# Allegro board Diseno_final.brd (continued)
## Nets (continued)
PHIDI_04: J1.11 R140.1
PHIDI_05: J1.2 R119.1
PHIDI_06: J1.3 R122.1
PHIDI_07: J1.4 R125.1
PHIDI_08: J1.5 R128.1
PHIDI_09: J5.8 R155.1
PHIDI_10: J5.9 R158.1
PHIDI_11: J5.10 R161.1
PHIDI_12: J5.11 R164.1
PHIDI_13: J5.2 R143.1
PHIDI_14: J5.3 R146.1
PHIDI_15: J5.4 R149.1
PHIDI_16: J5.5 R152.1
PHIDO_01: J9.8 R181.2
PHIDO_02: J9.9 R184.2
PHIDO_03: J9.10 R187.2
PHIDO_04: J9.11 R190.2
PHIDO_05: J9.2 R169.2
PHIDO_06: J9.3 R172.2
PHIDO_07: J9.4 R175.2
PHIDO_08: J9.5 R178.2
PHIDO_09: J13.8 R193.2
PHIDO_10: J13.9 R196.2
PHIDO_11: J13.10 R199.2
PHIDO_12: J13.11 R202.2
PHIDO_13: J13.2 R205.2
PHIDO_14: J13.3 R208.2
PHIDO_15: J13.4 R211.2
PHIDO_16: J13.5 R214.2
N74747: R120.1 U126.4(Y)
N74829: C157.1 R119.2 R121.1 U126.2(A) U184.3(C/A)
N79416: R123.1 U127.4(Y)
N79462: C158.1 R122.2 R124.1 U127.2(A) U185.3(C/A)
N79945: R126.1 U128.4(Y)
N79991: C159.1 R125.2 R127.1 U128.2(A) U186.3(C/A)
N80527: R129.1 U129.4(Y)
N80573: C160.1 R128.2 R130.1 U129.2(A) U187.3(C/A)
N81079: R131.1 U130.4(Y)
N81125: C161.1 R132.2 R133.1 U130.2(A) U188.3(C/A)
N81639: R134.1 U131.4(Y)
N81689: C162.1 R135.2 R136.1 U131.2(A) U189.3(C/A)
N82212: R137.1 U132.4(Y)
N82258: C163.1 R138.2 R139.1 U132.2(A) U190.3(C/A)
N84241: R141.1 U133.4(Y)
N84291: C164.1 R140.2 R142.1 U133.2(A) U191.3(C/A)
N85989: R168.1 U142.4(Y)
N86434: D65.A D66.C R168.2 R169.1
N87118: R171.1 U143.4(Y)
N87238: D67.A D68.C R171.2 R172.1
N87595: R174.1 U144.4(Y)
N87715: D69.A D70.C R174.2 R175.1
N88084: R177.1 U145.4(Y)
N88204: D71.A D72.C R177.2 R178.1
N88589: R180.1 U146.4(Y)
N88709: D73.A D74.C R180.2 R181.1
N89108: R183.1 U147.4(Y)
N89151: R147.1 U135.4(Y)
N89207: C166.1 R146.2 R148.1 U135.2(A) U193.3(C/A)
N89228: D75.A D76.C R183.2 R184.1
N89405: R150.1 U136.4(Y)
N89461: C167.1 R149.2 R151.1 U136.2(A) U194.3(C/A)
N89641: R186.1 U148.4(Y)
N89659: R153.1 U137.4(Y)
N89709: C168.1 R152.2 R154.1 U137.2(A) U195.3(C/A)
N89761: D77.A D78.C R186.2 R187.1
N89929: R156.1 U138.4(Y)
N89969: C169.1 R155.2 R157.1 U138.2(A) U196.3(C/A)
N90183: R159.1 U139.4(Y)
N90186: R189.1 U149.4(Y)
N90223: C170.1 R158.2 R160.1 U139.2(A) U197.3(C/A)
N90306: D79.A D80.C R189.2 R190.1
N90437: R162.1 U140.4(Y)
N90483: C171.1 R161.2 R163.1 U140.2(A) U198.3(C/A)
N90675: R165.1 U141.4(Y)
N90725: C172.1 R164.2 R166.1 U141.2(A) U199.3(C/A)
N90891: R144.1 U134.4(Y)
N90937: C165.1 R143.2 R145.1 U134.2(A) U192.3(C/A)
N91462: R192.1 U150.4(Y)
N91582: D81.A D82.C R192.2 R193.1
N91694: R195.1 U151.4(Y)
N91818: D83.A D84.C R195.2 R196.1
N91930: R198.1 U152.4(Y)
N92054: D85.A D86.C R198.2 R199.1
N92166: R201.1 U153.4(Y)
N92290: D87.A D88.C R201.2 R202.1
N92402: R204.1 U154.4(Y)
N92526: D89.A D90.C R204.2 R205.1
N92638: R207.1 U155.4(Y)
N92762: D91.A D92.C R207.2 R208.1
N92874: R210.1 U156.4(Y)
N92998: D93.A D94.C R210.2 R211.1
N93110: R213.1 U157.4(Y)
N93154: R79.1 U65.4(VREF) U66.6(OUT)
N93187: C89.2 U65.5(IOUT) U67.2(-IN)
N93234: D95.A D96.C R213.2 R214.1
N93303: C89.1 R82.1 U65.3(RFB) U67.6(OUT)
N93563: D17.A D18.C R82.2 R83.1
N101155: R80.1 R81.2 U64.2(V-)
N101611: R79.2 U66.2(-IN)
N101668: R81.1 U66.3(+IN)
N103431: C87.2 U63.2(VOUT) U67.7(V+)
N104801: R77.1 R78.2 U61.1(V+)
N105129: R78.1 U60.3(+IN_A)
N105257: R76.2 U60.4(-IN_A)
N105843: R5.1 R9.2 U160.3(C/A)
N106132: R5.2 U7.3(+IN)
N106136: R11.2 U7.2(-IN)
N106151: R7.2 R11.1 U7.6(OUT)
N106282: C9.1 R7.1 R8.2
N106462: C10.2 R8.1 U8.3(+IN)
N106606: C9.2 R6.2 R10.1 U8.6(OUT)
N106624: R10.2 R12.1 U8.2(-IN)
N106890: C7.2 U5.2(VOUT) U8.7(V+)
N107081: C5.2 U2.2(VOUT) U7.7(V+)
N108762: C12.2 U7.4(V-) U9.4(-OUT)
N108773: C14.2 U8.4(V-) U10.4(-OUT)
N109129: R6.1 U6.3(VIN)
N109578: R3.2 R223.1 U3.1(OUT)
N109817: C2.2 U1.2(VOUT) U3.5(V+)
N111654: R1.2 R2.1 U4.1(+)
N111746: R2.2 U3.3(+IN)
N111794: R3.1 U3.4(-IN)
N112163: U6.5(SDATA) U168.2(A)
N119962: J10.4 R83.2
N119975: J10.6 R87.2
N119987: J10.7 R93.2
N119999: J10.9 R97.2
N122542: R17.2 R18.1 U161.3(C/A)
N122562: R18.2 U14.3(+IN)
N122563: J14.4 R102.2
N122566: R20.2 U14.2(-IN)
N122567: J14.6 R107.2
N122571: J14.7 R112.2
N122574: R15.2 R20.1 U14.6(OUT)
N122575: J14.9 R117.2
N122594: C19.1 R15.1 R16.2
N122598: C20.2 R16.1 U15.3(+IN)
N122622: C19.2 R14.2 R19.1 U15.6(OUT)
N122634: R19.2 R21.1 U15.2(-IN)
N122662: C17.2 U12.2(VOUT) U15.7(V+)
N122690: C16.2 U11.2(VOUT) U14.7(V+)
N122954: C21.2 U14.4(V-) U16.4(-OUT)
N122958: C24.2 U15.4(V-) U17.4(-OUT)
N122962: R14.1 U13.3(VIN)
N122974: U13.5(SDATA) U169.2(A)
N123518: J3.4 R9.1
N123530: J3.6 R17.1
N123542: J3.7 R23.1
N123554: J3.9 R35.1
N124156: J7.4 R42.1
N124168: J7.6 R52.1
N124183: J7.7 R59.1
N124195: J7.9 R71.1
N124258: R84.1 U73.6(OUT) U74.4(VREF)
N124270: C98.2 U74.5(IOUT) U75.2(-IN)
N124298: C98.1 R86.1 U74.3(RFB) U75.6(OUT)
N124346: D19.A D20.C R86.2 R87.1
N124548: R85.1 R88.2 U72.2(V-)
N124568: R84.2 U73.2(-IN)
N124584: R88.1 U73.3(+IN)
N124764: C97.2 U71.2(VOUT) U75.7(V+)
N124930: R23.2 R27.1 U162.3(C/A)
N124958: R27.2 U21.3(+IN)
N124962: R29.2 U21.2(-IN)
N124970: R25.2 R29.1 U21.6(OUT)
N124990: C29.1 R25.1 R26.2
N124994: C30.2 R26.1 U22.3(+IN)
N125018: C29.2 R24.2 R28.1 U22.6(OUT)
N125030: R28.2 R30.1 U22.2(-IN)
N125058: C27.2 U19.2(VOUT) U22.7(V+)
N125086: C26.2 U18.2(VOUT) U21.7(V+)
N125344: C31.2 U21.4(V-) U23.4(-OUT)
N125348: C34.2 U22.4(V-) U24.4(-OUT)
N125358: R24.1 U20.3(VIN)
N125370: U20.5(SDATA) U170.2(A)
N127346: R35.2 R36.1 U163.3(C/A)
N127374: R36.2 U29.3(+IN)
N127378: R38.2 U29.2(-IN)
N127386: R33.2 R38.1 U29.6(OUT)
N127406: C39.1 R33.1 R34.2
N127410: C40.2 R34.1 U28.3(+IN)
N127434: C39.2 R32.2 R37.1 U28.6(OUT)
N127446: R37.2 R39.1 U28.2(-IN)
N127474: C37.2 U26.2(VOUT) U28.7(V+)
N127502: C36.2 U25.2(VOUT) U29.7(V+)
N127760: C41.2 U29.4(V-) U30.4(-OUT)
N127764: C44.2 U28.4(V-) U31.4(-OUT)
N127774: R32.1 U27.3(VIN)
N127786: U27.5(SDATA) U171.2(A)
N128052: R89.1 U81.4(VREF) U83.6(OUT)
N128064: C107.2 U81.5(IOUT) U82.2(-IN)
N128092: C107.1 R92.1 U81.3(RFB) U82.6(OUT)
N128132: D21.A D22.C R92.2 R93.1
N128330: R90.1 R91.2 U80.2(V-)
N128350: R89.2 U83.2(-IN)
N128366: R91.1 U83.3(+IN)
N128546: C106.2 U79.2(VOUT) U82.7(V+)
N130444: C116.2 U90.5(IOUT) U91.2(-IN)
N130448: R94.1 U89.6(OUT) U90.4(VREF)
N130476: C116.1 R96.1 U90.3(RFB) U91.6(OUT)
N130520: D23.A D24.C R96.2 R97.1
N130722: R95.1 R98.2 U88.2(V-)
N130734: R94.2 U89.2(-IN)
N130754: R98.1 U89.3(+IN)
N130926: C115.2 U87.2(VOUT) U91.7(V+)
N150307: C125.2 U98.5(IOUT) U99.2(-IN)
N150319: R99.1 U97.6(OUT) U98.4(VREF)
N150363: C125.1 R101.1 U98.3(RFB) U99.6(OUT)
N150395: D25.A D26.C R101.2 R102.1
N150597: R100.1 R103.2 U96.2(V-)
N150621: R99.2 U97.2(-IN)
N150641: R103.1 U97.3(+IN)
N150813: C124.2 U95.2(VOUT) U99.7(V+)
N151319: R42.2 R43.1 U164.3(C/A)
N151343: C134.2 U106.5(IOUT) U107.2(-IN)
N151347: R43.2 U36.3(+IN)
N151351: R47.2 U36.2(-IN)
N151355: R104.1 U105.6(OUT) U106.4(VREF)
N151359: R45.2 R47.1 U36.6(OUT)
N151379: C49.1 R41.2 R45.1
N151407: C49.2 R44.2 R46.1 U35.6(OUT)
N151415: D27.A D28.C R106.2 R107.1
N151419: R46.2 R48.1 U35.2(-IN)
N151447: C47.2 U33.2(VOUT) U35.7(V+)
N151475: C46.2 U32.2(VOUT) U36.7(V+)
N151623: R105.1 R108.2 U104.2(V-)
N151641: R104.2 U105.2(-IN)
N151661: R108.1 U105.3(+IN)
N151733: C51.2 U36.4(V-) U37.4(-OUT)
N151737: C54.2 U35.4(V-) U38.4(-OUT)
N151741: R44.1 U34.3(VIN)
N151759: U34.5(SDATA) U172.2(A)
N151833: C133.2 U103.2(VOUT) U107.7(V+)
N152345: R52.2 R54.1 U165.3(C/A)
N152363: C143.2 U114.5(IOUT) U115.2(-IN)
N152375: R109.1 U113.6(OUT) U114.4(VREF)
N152387: R54.2 U43.3(+IN)
N152391: R56.2 U43.2(-IN)
N152399: R50.2 R56.1 U43.6(OUT)
N152403: C143.1 R111.1 U114.3(RFB) U115.6(OUT)
N152419: C59.1 R50.1 R51.2
N152423: C60.2 R51.1 U42.3(+IN)
N152441: D29.A D30.C R111.2 R112.1
N152447: C59.2 R53.2 R55.1 U42.6(OUT)
N152459: R55.2 R57.1 U42.2(-IN)
N152487: C57.2 U40.2(VOUT) U42.7(V+)
N152515: C56.2 U39.2(VOUT) U43.7(V+)
N152649: R110.1 R113.2 U112.2(V-)
N152661: R109.2 U113.2(-IN)
N152681: R113.1 U113.3(+IN)
N152773: C61.2 U43.4(V-) U44.4(-OUT)
N152777: C64.2 U42.4(V-) U45.4(-OUT)
N152781: R53.1 U41.3(VIN)
N152799: U41.5(SDATA) U173.2(A)
N152853: C142.2 U111.2(VOUT) U115.7(V+)
N153383: C152.2 U122.5(IOUT) U123.2(-IN)
N153389: R59.2 R63.1 U166.3(C/A)
N153395: R114.1 U121.6(OUT) U122.4(VREF)
N153423: C152.1 R116.1 U122.3(RFB) U123.6(OUT)
N153431: R63.2 U50.3(+IN)
N153435: R65.2 U50.2(-IN)
N153443: R61.2 R65.1 U50.6(OUT)
N153455: D31.A D32.C R116.2 R117.1
N153463: C69.1 R61.1 R62.2
N153467: C70.2 R62.1 U49.3(+IN)
N153491: C69.2 R60.2 R64.1 U49.6(OUT)
N153503: R64.2 R66.1 U49.2(-IN)
N153531: C67.2 U47.2(VOUT) U49.7(V+)
N153559: C66.2 U46.2(VOUT) U50.7(V+)
N153663: R115.1 R118.2 U120.2(V-)
N153681: R114.2 U121.2(-IN)
N153701: R118.1 U121.3(+IN)
N153817: C71.2 U50.4(V-) U51.4(-OUT)
N153821: C74.2 U49.4(V-) U52.4(-OUT)
N153825: R60.1 U48.3(VIN)
N153843: U48.5(SDATA) U174.2(A)
N153873: C151.2 U119.2(VOUT) U123.7(V+)
N154443: R71.2 R72.1 U167.3(C/A)
N154471: R72.2 U56.3(+IN)
N154475: R74.2 U56.2(-IN)
N154483: R69.2 R74.1 U56.6(OUT)
N154503: C79.1 R69.1 R70.2
N154507: C80.2 R70.1 U57.3(+IN)
N154531: C79.2 R68.2 R73.1 U57.6(OUT)
N154543: R73.2 R75.1 U57.2(-IN)
N154571: C77.2 U54.2(VOUT) U57.7(V+)
N154599: C76.2 U53.2(VOUT) U56.7(V+)
N154857: C81.2 U56.4(V-) U58.4(-OUT)
N154861: C84.2 U57.4(V-) U59.4(-OUT)
N154865: R68.1 U55.3(VIN)
N154883: U55.5(SDATA) U175.2(A)
N183704: U65.2(SDI) U176.4(Y)
N189418: R4.1 U168.4(Y)
N189529: R40.1 U172.4(Y)
N189636: R13.1 U169.4(Y)
N189665: R49.1 U173.4(Y)
N189787: R22.1 U170.4(Y)
N189811: R58.1 U174.4(Y)
N189953: R31.1 U171.4(Y)
N189979: R67.1 U175.4(Y)
N190257: U74.2(SDI) U177.4(Y)
N190390: U98.2(SDI) U180.4(Y)
N190419: U81.2(SDI) U178.4(Y)
N190547: U106.2(SDI) U181.4(Y)
N190594: U90.2(SDI) U179.4(Y)
N190692: U114.2(SDI) U182.4(Y)
N190839: U122.2(SDI) U183.4(Y)
N222678: C91.2 U66.4(V-) U68.4(-OUT)
N222700: C127.2 U97.4(V-) U100.4(-OUT)
N224115: C129.2 U99.4(V-) U101.4(-OUT)
N224126: C93.2 U67.4(V-) U69.4(-OUT)
N225476: C100.2 U73.4(V-) U76.4(-OUT)
N225794: C136.2 U105.4(V-) U108.4(-OUT)
N226643: C102.2 U75.4(V-) U77.4(-OUT)
N226662: C138.2 U107.4(V-) U109.4(-OUT)
N227931: C109.2 U83.4(V-) U84.4(-OUT)
N229062: C111.2 U82.4(V-) U85.4(-OUT)
N230061: C118.2 U89.4(V-) U92.4(-OUT)
N231120: C120.2 U91.4(V-) U93.4(-OUT)
N231215: C154.2 U121.4(V-) U124.4(-OUT)
N232018: C156.2 U123.4(V-)
N233016: C145.2 U113.4(V-) U116.4(-OUT)
N233815: C147.2 U115.4(V-) U117.4(-OUT)
N255947: U300.3(VCCCIO0#3)

Pads without a net: U7 1 5 8; U8 1 5 8; U9 1 3; U10 1 3; U14 1 5 8; U15 1 5 8; U16 1 3; U17 1 3; U21 1 5 8; U22 1 5 8; U23 1 3; U24 1 3; U28 1 5 8; U29 1 5 8; U30 1 3; U31 1 3; U35 1 5 8; U36 1 5 8; U37 1 3; U38 1 3; U42 1 5 8; U43 1 5 8; U44 1 3; U45 1 3; U49 1 5 8; U50 1 5 8; U51 1 3; U52 1 3; U56 1 5 8; U57 1 5 8; U58 1 3; U59 1 3; U62 4; U66 1 5 8; U67 1 5 8; U68 1 3; U69 1 3; U73 1 5 8; U75 1 5 8; U76 1 3; U77 1 3; U82 1 5 8; U83 1 5 8; U84 1 3; U85 1 3; U89 1 5 8; U91 1 5 8; U92 1 3; U93 1 3; U97 1 5 8; U99 1 5 8; U100 1 3; U101 1 3; U105 1 5 8; U107 1 5 8; U108 1 3; U109 1 3; U113 1 5 8; U115 1 5 8; U116 1 3; U117 1 3; U121 1 5 8; U123 1 5 8; U124 1 3; U126 1; U127 1; U128 1; U129 1; U130 1; U131 1; U132 1; U133 1; U134 1; U135 1; U136 1; U137 1; U138 1; U139 1; U140 1; U141 1; U142 1; U143 1; U144 1; U145 1; U146 1; U147 1; U148 1; U149 1; U150 1; U151 1; U152 1; U153 1; U154 1; U155 1; U156 1; U157 1; U168 1; U169 1; U170 1; U171 1; U172 1; U173 1; U174 1; U175 1; U176 1; U177 1; U178 1; U179 1; U180 1; U181 1; U182 1; U183 1; U200 1; U201 1; U202 1; U203 1; U204 1; U205 1; U206 1; U207 1; U208 1; U209 1; U210 1; U211 1; U212 1; U213 1; U214 1; U215 1; U300 15 16 17 18 19 20 21 22 25 26 27 28 29 30 51 52 55 56 57 58 69 70 71 72 75 76 77 78 86 88 90 93 94 95 96 97 98 99 100 101 102 117 118 119 120 121 122 125 126 127 128 129 130 145 146 147 148 149 150 151 152 155 156 157 158 161 162 163 164; U301 1 4 5 6 7 8 10 12 13 15 17 18 19 20 21 24; U302 1 4 5 6 7 8 9 10 11 12 13 15 17 18 19 20 21 24

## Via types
v1: diameter 0.61, hole 0.33, TOP to BOTTOM, 885 vias

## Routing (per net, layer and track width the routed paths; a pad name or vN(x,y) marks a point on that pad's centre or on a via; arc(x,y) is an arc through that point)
3V3: length 493.2
  TOP w0.381: C237.1 119.56,48.45 118.58,47.47 v1(117.96,47.47) 117.27,48.16 U154.5 ; U202.5 v1(121.64,105.82) ; v1(100.33,40.69) 100.33,41.69 100.34,41.69 U144.5 ; U171.5 106.69,171.46 106.69,171.45 106.45,171.45 106.2,171.2 106.2,170.59 ; U138.5 55.27,53.29 v1(54.38,54.18) 53.24,54.18 52.93,53.87 C221.1 ; 106.2,170.59 v1(105.13,170.59) ; 106.2,170.59 106.2,169.91 107,169.11 C190.1 ; C192.1 v1(121.31,172.72) ; C206.1 v1(112.09,127.89) ; v1(122.05,87.53) 121.23,88.34 C241.1 ; C194.1 v1(105.36,107.21) 105.36,107.84 105.38,107.86 105.38,108.38 106.6,109.6 U173.5 ; C201.1 v1(111.96,148.62) ; U215.5 v1(121.94,162.27) ; v1(115.06,41.3) 115.41,41.65 U150.5 ; U132.5 38.84,53.24 v1(38.2,53.87) 37.36,53.87 36.68,53.19 C215.1 ; C203.1 v1(111.86,176) ; v1(133.05,41.21) 133.05,41.22 133.05,42.63 U153.5 ; C244.1 v1(121.95,123.39) ; C219.1 64.9,46.33 65.41,46.84 65.68,46.84 65.71,46.86 v1(66.4,46.86) 67.11,46.15 U136.5 ; C222.1 59.97,53.43 60.29,53.75 v1(61.54,53.75) 62.18,53.11 U139.5 ; C240.1 137.29,48.65 136.49,47.85 v1(135.41,47.85) 134.92,48.34 U157.5 ; C204.1 v1(121.95,158.65) ; U137.5 73.94,46.18 v1(73.25,46.86) 72.21,46.86 71.73,46.38 C220.1 ; U206.5 v1(106.49,165.9) ; C213.1 22.94,53.62 v1(23.93,54.61) 25.17,53.37 U130.5 ; C185.1 120.8,102.13 v1(121.67,101.27) ; U181.5 v1(112.11,131.55) ; U211.5 v1(121.36,120.02) ; U126.5 22.96,46.03 v1(22.33,46.66) 21.16,46.66 20.39,45.88 C209.1 ; C191.1 v1(106.5,162.33) ; U205.5 v1(112.45,145.29) ; U141.5 75.92,53.45 75.58,53.8 v1(74.96,53.8) 74.12,53.8 73.74,53.42 C224.1 ; C207.1 v1(112.04,155.37) ; U155.5 123.16,48.47 123.65,47.98 v1(123.65,47.96) 124.83,47.96 125.45,48.58 C238.1 ; v1(121.34,116.92) 120.93,116.51 C197.1 ; U131.5 32,53.3 31.64,53.67 v1(31.01,53.67) 30.34,53.67 29.77,53.1 C214.1 ; C202.1 v1(121.28,179.73) ; v1(121.46,94.36) 120.88,94.95 C243.1 ; v1(88.24,40.79) 88.29,40.79 88.57,41.07 U142.5 ; C242.1 v1(112.12,93.65) ; U174.5 115.86,139.83 114.83,138.8 v1(114.83,137.54) C195.1 ; C210.1 27.36,45.88 28.08,46.61 v1(29.41,46.61) 29.79,46.23 U127.5 ; C218.1 57.96,46.15 58.72,46.91 v1(59.61,46.91) 59.76,46.9 60.2,46.46 U135.5 ; U143.5 94.45,41.69 94.44,41.68 v1(94.44,40.72) ; v1(106.22,40.79) 106.22,41.5 U145.5 ; U203.5 v1(112.21,117.82) ; U156.5 129.04,48.79 v1(129.62,48.21) 130.97,48.21 131.37,48.6 C239.1 ; C186.1 v1(112.12,114.15) ; C198.1 v1(111.96,121.06) ; C181.1 v1(105.41,79.76) 105.41,80.88 106.69,82.16 U168.5 ; U183.5 v1(112.16,186.51) ; C223.1 66.93,53.23 67.37,53.67 v1(68.45,53.67) 69.09,53.04 U140.5 ; U178.5 v1(121.7,155.22) ; U148.5 102.22,48.28 v1(102.79,47.7) 103.67,47.7 104.6,48.63 C230.1 ; U207.5 v1(121.33,176.35) ; U204.5 v1(121.55,134.1) ; C231.1 110.44,48.34 109.75,47.65 v1(108.8,47.65) 108.1,48.35 U149.5 ; C217.1 51.05,46.23 51.74,46.91 v1(52.51,46.91) 53.29,46.14 U134.5 ; U179.5 v1(121.28,183.39) ; C189.1 v1(112.42,141.73) ; C205.1 v1(112.14,100.33) ; C187.1 v1(105.56,134.82) 105.56,136.02 106.66,137.11 U170.5 ; C193.1 116.13,81.15 v1(113.79,83.49) 116.8,83.49 U172.5 ; U176.5 v1(121.51,98.68) ; U201.5 v1(112.48,90.34) ; U152.5 127.18,41.43 126.72,40.97 v1(126.62,40.97) ; C211.1 34.11,46.05 34.82,46.76 v1(36,46.76) 36.63,46.14 U128.5 ; U209.5 v1(121.99,91.86) ; U200.5 v1(121.34,77.77) ; C184.1 116.05,110.01 v1(113.82,112.24) U169.5 ; 90.45,49.57 U146.5 90.45,48.62 91.21,47.85 v1(91.21,47.65) 91.26,47.6 92.02,47.6 92.74,48.31 C232.1 ; C182.1 v1(121.31,73.89) ; U214.5 v1(111.87,179.64) ; C216.1 43.46,53.44 43.81,53.8 v1(45.19,53.8) 45.67,53.31 U133.5 ; C183.1 v1(112.29,86.72) ; U147.5 96.33,47.99 v1(96.65,47.68) 97.68,47.68 98.63,48.63 C229.1 ; C200.1 v1(121.87,144.6) ; C196.1 v1(114.83,165.71) 114.83,167 115.83,168 U175.5 ; C212.1 41.12,45.9 41.99,46.76 v1(43.08,46.76) 43.46,46.38 U129.5 ; U182.5 v1(112.06,159.03) ; C199.1 v1(121.79,151.56) ; U212.5 v1(112.05,152.16) ; C188.1 v1(121.51,130.43) ; U210.5 v1(112.06,124.68) ; v1(120.83,40.94) 121.29,41.41 U151.5 ; U213.5 v1(121.79,148.18) ; C208.1 v1(111.81,182.83) ; U208.5 v1(112.2,97.21) ; U180.5 v1(112,104.08) ; U177.5 v1(122.11,127.06)
  VCC w0.127: J9.7 91.34,17.51 ; J9.7 92.22,16.64 ; J9.7 90.46,16.64 ; J9.7 91.34,15.76 ; U302.14 61.42,162.25 ; U302.14 60.41,161.24 ; U302.14 60.41,163.27 ; U302.14 59.39,162.25 ; J5.7 56.63,16.64 ; J5.7 54.88,16.64 ; J5.7 55.75,15.76 ; J5.7 55.75,17.51 ; J5.6 69.33,14.1 ; J5.6 68.45,14.97 ; J5.6 67.58,14.1 ; J5.6 68.45,13.22 ; 103.16,14.1 J9.6 ; J9.6 104.92,14.1 ; J9.6 104.04,13.22 ; J9.6 104.04,14.97 ; 113.32,16.64 J13.7 ; J13.7 114.2,17.51 ; J13.7 114.2,15.76 ; J13.7 115.08,16.64 ; J1.6 45.59,14.97 ; J1.6 45.59,13.22 ; J1.6 46.47,14.1 ; J1.6 44.72,14.1 ; J13.6 127.78,14.1 ; J13.6 126.02,14.1 ; J13.6 126.9,14.97 ; J13.6 126.9,13.22 ; 32.89,15.76 J1.7 ; J1.7 32.02,16.64 ; J1.7 33.77,16.64 ; J1.7 32.89,17.51
  BOTTOM w0.381: v1(31.01,53.67) 31.87,52.81 U185.2 ; R209.2 v1(128.75,62.48) ; v1(126.62,40.97) 126.18,40.97 ; 126.18,40.97 124.54,40.97 123.67,41.83 C235.1 ; 126.18,40.97 125.94,40.73 D85.C ; C227.1 96.75,41.95 97.57,41.13 99.89,41.13 v1(100.33,40.69) 99.58,40.69 99.12,40.22 D69.C ; D89.C 117.19,40.52 v1(116.36,41.35) ; C233.1 111.81,41.95 112.46,41.3 v1(115.06,41.3) 114.62,40.86 114.62,40.82 114.27,40.47 D81.C ; v1(107.77,65.68) 104.83,62.74 R176.2 ; 132.27,41.15 132.33,41.21 v1(133.05,41.21) ; 132.27,41.15 131.77,40.65 D87.C ; 132.27,41.15 130.18,41.15 129.54,41.78 C236.1 ; R188.2 107.72,63.35 v1(108.89,64.52) ; C226.1 90.91,42.21 91.36,41.76 93.4,41.76 v1(94.44,40.72) 93.81,40.72 93.28,40.19 D67.C ; U196.2 59,55.7 59.33,56.03 v1(61.11,56.03) ; v1(102.72,40.64) 102.71,40.64 102.03,39.96 D77.C ; v1(74.68,56.01) 73.15,56.01 72.8,55.66 U198.2 ; v1(61.54,53.75) 62.04,53.25 U193.2 ; U189.2 35.22,55.64 35.59,56.01 36.15,56.01 36.59,55.56 v1(36.59,54.94) ; v1(96.93,40.69) 96.2,39.96 D75.C ; v1(67.84,56.09) 66.17,56.09 65.9,55.82 U197.2 ; R206.2 v1(122.96,63.3) ; R173.2 v1(99.03,62.79) ; R203.2 v1(117.17,63.32) ; v1(50.57,55.65) 50.01,56.21 49.59,56.21 49.02,55.64 U191.2 ; C234.1 117.73,41.97 118.78,40.92 119.02,40.92 119.05,40.94 120.36,40.94 ; R200.2 v1(131.65,62.41) ; R185.2 v1(101.93,62.79) ; U188.2 28.32,55.64 28.63,55.95 29.17,55.95 v1(29.79,55.32) ; D83.C 120.11,40.69 120.36,40.94 ; 120.36,40.94 v1(120.83,40.94) ; R197.2 v1(125.86,62.48) ; v1(108.74,41) 107.86,40.12 D79.C ; R167.2 v1(87.45,62.69) ; R179.2 v1(90.35,62.66) ; U195.2 75.84,52.91 v1(74.96,53.8) ; U186.2 38.77,53.31 v1(38.2,53.87) ; v1(23.93,54.61) 23.93,53.99 24.97,52.95 U184.2 ; v1(127.91,41.11) 128.53,41.11 128.85,40.79 D93.C ; D91.C 123.02,40.85 122.67,41.2 v1(122.05,41.2) ; v1(54.38,54.18) 55.14,53.42 U192.2 ; v1(81.46,55.02) 80.54,55.93 80,55.93 79.7,55.64 U199.2 ; U194.2 68.94,53.18 v1(68.45,53.67) ; v1(45.19,53.8) 45.67,53.31 U187.2 ; U190.2 42.12,55.64 42.4,55.92 42.99,55.92 v1(43.64,55.27) ; R194.2 v1(120.07,63.37) ; D95.C 134.69,40.63 v1(135.56,41.5) ; D71.C 104.95,40.14 105.6,40.79 v1(106.22,40.79) 105.64,41.38 103.09,41.38 102.57,41.9 C228.1 ; R191.2 v1(114.27,63.27) ; D65.C 87.45,39.96 87.8,40.31 87.8,40.35 v1(88.24,40.79) 86.12,40.79 84.86,42.05 C225.1 ; D73.C 90.37,39.96 v1(91.25,40.84) ; R170.2 v1(93.24,62.64) ; R212.2 v1(134.54,62.43) ; R182.2 v1(96.14,62.71)
3V3ADC: length 88.7
  TOP w0.381: 155.6,153.29 156.55,153.29 156.71,153.14 v1(158.06,153.14) ; v1(157.66,112.5) 156.81,112.5 156.55,112.75 U13.1 ; v1(193.32,71.79) 192.38,71.79 192.04,72.14 U34.1 ; U6.1 156.55,72.14 156.83,71.86 v1(157.58,71.86) ; U55.1 192.44,194.72 192.8,194.36 v1(193.42,194.36) ; v1(193.34,112.47) 192.32,112.47 192.04,112.75 U41.1 ; 191.08,153.29 192.04,153.29 192.32,153.01 v1(193.17,153.01) ; v1(157.81,194.45) 156.82,194.45 156.55,194.72 U27.1
  BOTTOM w0.381: v1(193.14,170.66) 191.97,169.49 ; C174.2 156.1,110.62 157.66,112.18 v1(157.66,112.5) ; C173.2 156.04,70.03 157.58,71.56 v1(157.58,71.86) ; C177.2 191.63,70.1 v1(193.32,71.79) ; v1(193.34,112.47) 192.9,112.03 192.89,112.03 191.76,110.9 C178.2 ; C175.2 156.1,151.16 157.62,152.68 157.62,152.7 v1(158.06,153.14) ; C179.2 191.31,151.16 v1(193.17,153.01) ; v1(193.42,194.36) 192.98,193.92 192.97,193.92 191.6,192.56 C180.2 ; 158.47,162.43 v1(156.77,162.43) ; v1(157.81,194.45) 155.79,192.43 C176.2 ; 181.03,160.66 180.23,159.86 R223.2 176.95,159.86
  BOTTOM w1.143: 191.97,169.49 190.8,168.33 188.7,168.33 181.03,160.66 ; 176.95,159.86 168.41,159.86 165.84,162.43 158.47,162.43
3V3DAC: length 56.1
  TOP w0.381: U81.7 233.38,141.48 234.31,140.54 v1(235.2,140.54) ; U106.7 265.91,107.21 266.85,106.27 v1(267.74,106.27) ; U90.7 233.38,175.51 234.31,174.57 v1(235.2,174.57) ; v1(267.74,74.6) 266.85,74.6 265.91,75.54 U98.7 ; U122.7 265.91,175.51 266.85,174.57 v1(267.74,174.57) ; U114.7 265.91,141.48 266.85,140.54 v1(267.74,140.54) ; v1(235.2,106.27) 234.31,106.27 233.38,107.21 U74.7 ; v1(235.2,74.6) 234.31,74.6 233.38,75.54 U65.7
  BOTTOM w0.381: v1(269.06,125.27) 269.02,125.23 269.02,124.38 269.47,123.92 ; 274.05,121.37 274.64,120.78 C86.2 ; 274.05,124.68 274.95,125.58 U62.5 ; v1(255.55,123.92) 256.97,123.92
  BOTTOM w1.27: 274.05,123.92 256.97,123.92 ; 274.05,123.92 274.05,124.68 ; 274.05,123.92 274.05,121.37
3VPROT: length 206.2
  BOTTOM w0.381: 151.76,34.63 152.16,34.24 ; 151.76,34.63 151.76,34.54 151.38,34.16 148.92,34.16 148.46,34.62 U60.1 ; 151.76,34.63 R76.1 ; U166.2 199.22,28.3 198.83,28.69 198.83,29.18 ; 169.65,28.68 169.65,28.33 169.94,28.04 U162.2 ; U165.2 192.65,28.3 192.23,28.71 192.23,29.11 ; 154.91,28.96 154.91,28.44 155.31,28.04 U160.2 ; 185.95,29.11 185.95,28.79 186.47,28.27 U164.2 ; D31.C 268.17,24.41 267.65,23.88 ; U167.2 205.63,28.32 205.13,28.82 205.13,29.24 ; D27.C 257.68,23.88 ; 224.46,24.69 D17.C ; 234.39,24.56 D21.C ; 176.5,28.78 176.5,28.36 176.82,28.04 U163.2 ; 229.39,24.49 D19.C ; 162.99,28.54 163.49,28.04 U161.2 ; 252.76,23.88 D25.C ; 239.88,24.79 D23.C ; D29.C 262.66,23.88
  BOTTOM w0.762: 152.16,34.24 196.98,34.24 197,34.26 207.11,34.26 207.14,34.24 210.13,34.24 220.47,23.9 224.46,23.9 ; 234.39,23.88 239.88,23.88 ; 234.39,23.88 229.41,23.88 229.39,23.9 ; 234.39,23.88 234.39,23.88 234.39,24.56 ; 239.88,23.88 267.65,23.88 ; 239.88,23.88 239.88,24.79 ; 229.39,23.9 229.39,24.49 ; 229.39,23.9 224.46,23.9 ; 224.46,23.9 224.46,24.69
  BOTTOM w0.889: 205.13,34.26 205.13,29.24 ; 198.83,29.18 198.83,34.24 198.81,34.26 ; 192.23,34.24 192.23,29.11 ; 169.65,34.24 169.65,28.68 ; 185.85,34.24 185.95,34.14 185.95,29.11 ; 176.5,28.78 176.5,34.19 176.45,34.24 ; 162.99,28.54 162.79,28.74 162.79,34.24 ; 154.91,28.96 154.91,34.24
5VU: length 188.6
  TOP w0.254: 37.31,131.48 37.81,130.98 U300.83 ; 37.31,131.48 37.05,131.48 36.81,131.24 U300.81 ; 37.31,131.48 38.05,131.48 38.31,131.22 U300.84 ; 37.31,131.48 U300.82
  TOP w0.381: v1(132.84,186.39) 132.84,187.01 132.79,187.06 132.79,190.88 ; v1(18.87,147.96) 18.87,149.3 ; 37.31,131.48 v1(37.31,132.84) ; 23.22,192.81 v1(23.22,190.27)
  TOP w1.27: 18.87,149.3 18.87,150.7 ; 18.87,150.7 17.38,150.7 16.11,151.97 U303.1_1 ; 18.87,150.7 20.95,150.7 22.11,151.85 U303.1_2
  TOP w2.54: 132.79,190.88 127.3,196.37 26.77,196.37 23.22,192.81
  VCC w0.127: J10.2 228.26,16.64 ; J10.2 227.38,15.76 ; J10.2 226.5,16.64 ; J10.2 227.38,17.51 ; 36.53,162.25 U302.23 ; U302.23 37.55,163.27 ; U302.23 38.56,162.25 ; U302.23 37.55,161.24 ; J14.11 262.94,14.97 ; J14.11 262.94,13.22 ; J14.11 263.82,14.1 ; J14.11 262.06,14.1 ; J14.2 250.24,17.51 ; J14.2 250.24,15.76 ; J14.2 251.12,16.64 ; J14.2 249.36,16.64 ; J3.2 168.77,16.64 ; J3.2 167.89,17.51 ; J3.2 167.89,15.76 ; J3.2 167.02,16.64 ; 39.07,187.63 U301.22 ; U301.22 40.09,188.65 ; U301.22 40.09,186.61 ; U301.22 41.1,187.63 ; 36.53,187.63 U301.23 ; U301.23 37.55,186.61 ; U301.23 38.56,187.63 ; U301.23 37.55,188.65 ; J7.11 204.33,14.1 ; J7.11 203.45,13.22 ; J7.11 203.45,14.97 ; J7.11 202.58,14.1 ; J10.11 240.08,14.97 ; J10.11 240.96,14.1 ; J10.11 239.2,14.1 ; J10.11 240.08,13.22 ; 39.07,162.25 U302.22 ; U302.22 40.09,163.27 ; U302.22 41.1,162.25 ; U302.22 40.09,161.24 ; 190.75,15.76 J7.2 ; J7.2 190.75,17.51 ; J7.2 189.88,16.64 ; J7.2 191.63,16.64 ; 180.59,13.22 J3.11 ; J3.11 181.47,14.1 ; J3.11 180.59,14.97 ; J3.11 179.72,14.1
+5V: length 320.7
  VCC w0.127: 59.39,187.63 U301.14 ; U301.14 60.41,186.61 ; U301.14 60.41,188.65 ; U301.14 61.42,187.63
  BOTTOM w0.381: v1(280.62,70.82) 279.5,70.82 ; 146.35,62.41 146.74,62.79 U5.3 ; 174.83,174.42 v1(175.9,174.42) ; 181.86,181.45 182.4,180.92 C78.2 ; C150.2 274.22,172.92 274.76,172.38 ; 146.15,175.92 146.69,176.46 U25.3 ; U12.3 146.61,103.4 146.07,102.86 ; 146.25,134.65 146.63,135.03 147.05,135.03 147.05,135.03 U18.3 ; 146.07,99.49 146.61,98.95 C18.2 ; 146.35,58.87 146.89,58.34 C8.2 ; v1(279.4,136.86) 277.93,136.86 ; 146.13,131.37 146.91,130.58 C25.2 ; 145.06,132.69 v1(144.04,132.69) ; C132.2 274.34,104.62 274.88,104.08 ; C15.2 146.91,90.04 146.3,90.65 ; 245.97,102.87 246.02,102.92 v1(248.44,102.92) ; 178.46,183.13 v1(177.34,183.13) ; 178.23,144.02 178.21,144.02 v1(177.5,144.73) ; C35.2 146.91,172.01 146.15,172.77 ; 181.71,143.18 182.47,143.94 U47.3 ; 272.03,134.7 U111.3 274.14,134.7 ; 240.28,72.95 C88.2 241.35,72.95 241.58,72.72 ; v1(176.99,101.17) 178.26,101.17 ; 272.64,72.95 C123.2 273.94,72.95 274.62,72.26 ; 178.46,60.4 v1(177.11,60.4) ; 274.88,101.04 274.27,100.43 U103.3 272.06,100.43 ; v1(285,122.39) C85.2 281.14,122.39 279.83,123.7 U62.3 ; 146.43,50.11 147.12,49.43 C4.2 ; U2.3 147.05,53.88 146.43,53.26 ; 172.64,166.47 R1.1 172.64,167.79 v1(171.98,168.45) ; v1(176.63,92.15) 178.05,92.15 ; 181.86,184.76 182.45,185.34 183.64,185.34 ; 182.16,139.47 183.56,139.47 C68.2 ; 145.11,60.48 v1(144.15,60.48) ; 241.58,135.25 241.02,134.7 U79.3 239.42,134.7 ; U39.3 182.23,94.5 181.58,93.85 ; 182.32,172.01 C75.2 183.62,172.01 ; U119.3 274.04,168.73 ; 172.1,171.85 172.68,171.27 U1.3 173.71,171.27 ; v1(177.24,180.54) 178.28,180.54 ; 272.77,138.89 C141.2 274.35,138.89 274.88,138.35 ; 245.26,167.23 245.29,167.23 v1(246.46,166.07) ; 241.91,69.3 241.37,68.76 U63.3 239.45,68.76 ; 146.3,93.75 147.05,94.5 U11.3 ; U60.5 v1(148.46,40.36) ; U40.3 182.35,103.4 181.79,102.84 ; 145.82,140.03 146.36,139.49 C28.2 ; v1(280.47,102.77) 278.82,102.77 ; 239.47,100.43 U71.3 241.12,100.43 241.22,100.53 ; 181.86,62.11 182.54,62.79 U33.3 ; 241.97,138.35 241.43,138.89 C105.2 240.28,138.89 ; 241.63,169.11 241.25,168.73 U87.3 239.52,168.73 ; 241.76,104.62 C96.2 240.18,104.62 ; 182.2,58.34 183.57,58.34 C48.2 ; 144.68,141.71 v1(143.56,141.71) ; C45.2 182.35,49.43 181.81,49.97 ; 271.91,68.76 U95.3 274.02,68.76 ; 146.35,181.45 146.89,180.92 C38.2 ; U32.3 182.25,53.88 181.91,53.54 ; C55.2 182.22,90.04 ; 182.02,176.45 183.51,176.45 U53.3 ; U19.3 146.2,143.94 ; v1(280.42,126.8) 280.42,126.17 279.82,125.58 U62.1 ; v1(248.44,71.09) 246.84,71.09 ; C58.2 182.13,98.95 ; 241.63,172.41 241.11,172.92 C114.2 240.23,172.92 ; v1(176.99,132.56) 178.16,132.56 ; 144.53,183.16 v1(143.28,183.16) ; 145.03,51.51 v1(143.89,51.51) ; v1(247.47,137.11) 246.23,137.11 ; 178.82,51.56 v1(177.34,51.56) ; C1.2 172.49,177.11 ; U26.3 146.74,185.37 ; 145.21,92.13 v1(144.07,92.13) ; 144.75,174.27 v1(143.69,174.27) ; U46.3 182.54,135.03 182,134.5 ; 145.03,101.02 v1(143.69,101.02) ; R77.2 v1(152.42,31.15) ; C65.2 182.38,130.58 ; v1(278.76,170.99) 277.5,170.99
  BOTTOM w0.762: 182.2,58.34 181.86,58.68 181.86,60.4 ; 181.86,183.13 178.46,183.13 ; 181.86,183.13 181.86,184.76 ; 181.86,183.13 181.86,181.45 ; 242.12,102.87 242.12,104.26 241.76,104.62 ; 242.12,102.87 245.97,102.87 ; 242.12,102.87 242.12,101.43 241.22,100.53 ; 241.91,69.3 241.91,71.08 241.89,71.09 ; 245.26,167.23 241.76,170.74 241.63,170.74 ; 146.35,183.16 146.35,184.99 146.74,185.37 ; 146.35,183.16 146.35,181.45 ; 146.35,183.16 144.53,183.16 ; 279.5,70.82 274.62,70.82 ; 274.62,70.82 274.62,72.26 ; 274.62,70.82 274.62,69.37 274.02,68.76 ; 146.15,174.27 146.15,175.92 ; 146.15,174.27 144.75,174.27 ; 146.15,174.27 146.15,172.77 ; 181.71,143.18 181.71,141.48 ; 181.71,141.48 181.71,139.92 182.16,139.47 ; 181.71,141.48 180.77,141.48 178.23,144.02 ; 274.88,101.04 274.88,102.77 ; 274.88,102.77 274.88,104.08 ; 274.88,102.77 278.82,102.77 ; 146.35,62.41 146.35,60.48 ; 146.35,60.48 146.35,58.87 ; 146.35,60.48 145.11,60.48 ; 274.14,134.7 274.88,135.44 274.88,136.86 ; 181.86,60.4 178.46,60.4 ; 181.86,60.4 181.86,62.11 ; 274.88,138.35 274.88,136.86 ; 274.88,136.86 277.93,136.86 ; 241.63,172.41 241.63,170.74 ; 241.63,170.74 241.63,169.11 ; 277.5,170.99 274.76,170.99 ; 274.76,170.99 274.76,169.45 274.04,168.73 ; 274.76,170.99 274.76,172.38 ; 146.3,92.13 146.3,93.75 ; 146.3,92.13 145.21,92.13 ; 146.3,92.13 146.3,90.65 ; 182.32,172.01 182.02,172.31 182.02,177.95 179.43,180.54 178.28,180.54 ; 181.81,51.56 181.81,53.44 181.91,53.54 ; 181.81,51.56 181.81,49.97 ; 181.81,51.56 178.82,51.56 ; 146.13,131.37 146.13,132.69 ; 146.13,132.69 145.06,132.69 ; 146.13,132.69 146.13,134.52 146.25,134.65 ; 146.43,51.51 145.03,51.51 ; 146.43,51.51 146.43,53.26 ; 146.43,51.51 146.43,50.11 ; 172.1,171.85 172.1,174.42 ; 172.1,174.42 172.1,176.73 172.49,177.11 ; 172.1,174.42 174.83,174.42 ; 178.26,101.17 181.79,101.17 ; 181.79,101.17 181.79,99.29 182.13,98.95 ; 181.79,101.17 181.79,102.84 ; 246.23,137.11 241.97,137.11 ; 241.97,137.11 241.97,138.35 ; 241.97,137.11 241.97,135.64 241.58,135.25 ; 182.38,130.58 182,130.96 182,132.56 ; 145.82,141.71 145.82,143.56 146.2,143.94 ; 145.82,141.71 144.68,141.71 ; 145.82,141.71 145.82,140.03 ; 241.89,71.09 246.84,71.09 ; 241.89,71.09 241.89,72.41 241.58,72.72 ; 181.58,93.85 181.58,92.15 ; 181.58,92.15 181.58,90.68 182.22,90.04 ; 181.58,92.15 178.05,92.15 ; 178.16,132.56 182,132.56 ; 182,132.56 182,134.5 ; 146.07,101.02 145.03,101.02 ; 146.07,101.02 146.07,102.86 ; 146.07,101.02 146.07,99.49
-5V: length 263.5
  VCC w0.127: U301.11 60.41,173.41 ; U301.11 59.39,172.39 ; U301.11 60.41,171.37 ; U301.11 61.42,172.39
  VCC w0.381: 153.34,190.73 v1(153.34,189.18)
  VCC w1.27: 153.34,192.02 153.34,190.73
  BOTTOM w0.381: U10.5 163.14,59.64 162.71,60.07 162.71,62.2 163.09,62.59 C13.2 164.12,64.61 v1(164.52,65) ; 256.03,174.47 256.01,174.45 C153.2 v1(256.01,171.45) ; U100.5 255.63,75.77 256.01,75.39 C126.2 v1(256.01,71.32) ; C82.2 198.3,177.29 197.92,176.91 197.92,175.44 ; C22.2 162.81,95.33 162.43,94.94 162.43,93.42 ; 223.09,107.44 223.47,107.06 C99.2 ; 223.09,107.44 223.27,107.44 v1(223.98,108.15) ; 223.09,107.44 U76.5 ; v1(254.11,126.36) R110.2 254.11,129.47 254.77,130.12 255.63,130.12 256.01,130.51 C146.2 256.01,133.69 255.38,134.32 U117.5 ; 256.01,167.11 C155.2 256.01,164.61 255.96,164.56 255.96,164.47 255.52,164.03 254.64,164.03 254.11,163.5 R115.2 v1(254.11,160.46) ; v1(256.01,103.09) C135.2 256.01,107.06 255.63,107.44 U108.5 ; 162.43,93.42 v1(164.11,93.42) ; 162.43,93.42 162.43,93 163.49,91.95 U16.5 ; C62.2 198.3,95.33 197.92,94.94 197.92,93.57 ; 197.92,93.57 197.92,93 198.97,91.95 U44.5 ; 197.92,93.57 v1(199.77,93.57) ; U85.5 222.85,134.32 223.47,133.69 C110.2 223.47,130.51 223.09,130.12 222.23,130.12 221.57,129.47 R90.2 v1(219.46,128.4) ; U58.5 198.97,173.91 197.92,174.97 197.92,175.44 ; C52.2 198.3,54.71 197.92,54.33 197.92,52.91 ; v1(219.58,62.46) 220.21,62.46 220.21,62.46 R80.2 221.57,63.53 222.23,64.19 223.09,64.19 223.47,64.57 C92.2 223.47,67.75 222.85,68.38 U69.5 ; U59.5 198.63,182.22 198.2,182.65 198.2,184.78 198.58,185.17 C83.2 199.61,186.83 199.85,187.07 v1(199.85,187.53) ; v1(164.29,146.33) 164.29,145.71 164.12,145.54 C33.2 163.09,143.74 162.71,143.36 162.71,141.22 163.14,140.79 U24.5 ; U101.5 255.38,68.38 256.01,67.75 C128.2 256.01,64.57 255.63,64.19 254.77,64.19 254.11,63.53 R100.2 v1(254.11,60.16) ; 223.47,75.39 C90.2 ; 223.47,75.39 223.09,75.77 U68.5 ; 223.47,75.39 223.47,75.75 v1(224.03,76.3) ; U109.5 255.38,100.05 256.01,99.42 C137.2 256.01,96.24 255.63,95.86 254.77,95.86 254.11,95.2 R105.2 v1(254.11,91.91) ; 162.43,52.88 162.43,52.39 163.49,51.33 U9.5 ; 162.43,52.88 162.43,54.33 162.81,54.71 C11.2 ; 162.43,52.88 v1(164.21,52.88) ; 223.09,141.71 223.34,141.71 v1(224.03,142.39) ; 223.09,141.71 U84.5 ; 223.09,141.71 223.47,141.33 C108.2 ; 256.01,167.97 255.63,168.35 254.43,168.35 ; U31.5 163.14,182.22 162.71,182.65 162.71,184.78 163.09,185.17 C43.2 164.12,186.72 164.44,187.03 v1(164.44,187.66) ; 256.03,175.44 255.73,175.74 U124.5 ; 162.43,134.01 v1(163.91,134.01) ; 162.43,134.01 162.43,133.54 163.49,132.49 U23.5 ; 162.43,134.01 162.43,135.48 162.81,135.86 C32.2 ; 197.92,175.44 v1(199.64,175.44) ; U77.5 222.85,100.05 223.47,99.42 C101.2 223.47,96.24 223.09,95.86 222.23,95.86 221.57,95.2 R85.2 v1(219.66,94.13) ; 223.47,175.36 223.09,175.74 U92.5 ; 223.47,175.36 223.9,175.79 v1(223.9,176.73) ; 223.47,175.36 C117.2 ; v1(255.98,137.16) 255.98,137.78 256.01,137.81 C144.2 256.01,141.33 255.63,141.71 U116.5 ; 162.43,175.41 162.43,174.97 163.49,173.91 U30.5 ; 162.43,175.41 162.43,176.91 162.81,177.29 C42.2 ; 162.43,175.41 v1(163.96,175.41) ; U17.5 163.14,100.25 162.71,100.69 162.71,102.82 163.09,103.2 C23.2 164.12,105.07 v1(164.41,105.36) ; U37.5 198.97,51.33 197.92,52.39 197.92,52.91 ; v1(219.41,162.43) R95.2 221.57,163.5 222.23,164.16 223.09,164.16 223.47,164.54 C119.2 223.47,167.72 222.85,168.35 U93.5 ; U38.5 198.63,59.64 198.2,60.07 198.2,62.2 198.58,62.59 C53.2 199.61,64.4 199.9,64.69 v1(199.9,65.07) ; 197.92,134.01 197.92,135.48 198.3,135.86 C72.2 ; 197.92,134.01 197.92,133.54 198.97,132.49 U51.5 ; 197.92,134.01 v1(199.52,134.01) ; v1(199.87,146.43) 199.88,146.42 199.88,145.88 199.61,145.61 C73.2 198.58,143.74 198.2,143.36 198.2,141.22 198.63,140.79 U52.5 ; v1(199.87,105.31) 199.87,104.9 199.61,104.64 C63.2 198.58,103.2 198.2,102.82 198.2,100.69 198.63,100.25 U45.5 ; 197.92,52.91 v1(199.64,52.91)
  BOTTOM w0.762: 256.03,174.47 256.03,175.44 ; 256.01,167.97 256.01,167.11
/CS_I: length 221.9
  TOP w0.254: U300.132 50.81,124.01
  TOP w0.381: U204.2 v1(113.21,133.16) ; 50.81,124.01 50.8,124.01 50.8,117.54 50.81,117.53 50.81,117.44 57.4,110.85 67.84,110.85 71.7,114.71 J15.9 84.32,114.71 84.32,114.71 85.17,114.71 85.18,114.71 v1(85.8,114.71) ; U200.2 99.49,76.83 v1(94.08,82.25) ; U202.2 v1(113.54,104.88) ; U206.2 v1(99.83,164.96)
  BOTTOM w0.381: 91.16,105.54 112.88,105.54 v1(113.54,104.88) ; 91.16,105.54 91.16,85.17 v1(94.08,82.25) ; 91.16,105.54 91.16,114.71 ; 90.35,133.16 91.16,132.35 91.16,114.71 ; 90.35,133.16 v1(113.21,133.16) ; 90.35,133.16 90.35,159.46 95.83,164.95 99.24,164.95 99.25,164.96 v1(99.83,164.96) ; 91.16,114.71 86.43,114.71 86.42,114.71 v1(85.8,114.71)
/CS_I_1: length 84.7
  TOP w0.381: U6.6 v1(151.23,72.14) ; v1(123.42,75.9) U200.4 ; U34.6 v1(185.17,72.14)
  BOTTOM w0.381: v1(185.17,72.14) 168.5,72.14 165.05,68.68 145.26,68.68 141.81,72.14 ; 141.81,72.14 132.03,72.14 128.27,75.9 v1(123.42,75.9) ; 141.81,72.14 v1(151.23,72.14)
/CS_I_2: length 99.4
  TOP w0.381: U13.6 v1(150.83,112.75) ; v1(121.87,103.94) U202.4 ; U41.6 v1(185.29,112.75)
  BOTTOM w0.381: 128.09,108.46 132.38,112.75 v1(150.83,112.75) ; 128.09,108.46 128.07,108.46 123.55,103.94 v1(121.87,103.94) ; 128.09,108.46 165.61,108.46 169.9,112.75 v1(185.29,112.75)
/CS_I_3: length 84.9
  TOP w0.381: v1(123.24,132.23) 122.05,132.23 122.04,132.22 U204.4 ; 188.49,153.29 v1(185.06,153.29) ; 153.01,153.29 v1(151.36,153.29)
  BOTTOM w0.381: 147.49,149.42 166.26,149.42 170.13,153.29 v1(185.06,153.29) ; 147.49,149.42 130.3,132.23 v1(123.24,132.23) ; 147.49,149.42 v1(151.36,153.29)
/CS_I_4: length 160.4
  TOP w0.381: U206.4 105.37,164.02 105.39,164.03 v1(113.59,164.03) 120.93,164.03 151.61,194.72 U27.6 ; U55.6 185.27,194.72 v1(184.53,193.98)
  BOTTOM w0.381: v1(184.53,193.98) 164.29,193.98 158.75,188.44 158.75,168.86 157.84,167.94 146.33,167.94 142.42,164.03 v1(113.59,164.03)
/CS_O: length 214.5
  TOP w0.254: U300.108 50.31,130.78 50.32,130.78
  TOP w0.381: 95.94,156.79 v1(95,156.79) ; 95.94,156.79 v1(95.94,161.32) ; 95.94,156.79 95.94,147.22 ; v1(100.94,119.35) 101.56,119.35 101.57,119.35 112.83,119.35 113.1,119.08 U211.2 ; 95.94,147.22 95.94,119.35 ; 95.94,147.22 95.96,147.24 v1(97.38,147.24) ; 95.94,119.35 95.94,119.35 v1(96.72,119.35) ; 95.94,119.35 95.94,95.15 99.09,92 114.25,92 115.33,90.92 U209.2 ; U213.2 v1(100.58,147.24) ; U215.2 114.26,161.33 114.25,161.33 v1(113.63,161.33) ; 50.32,130.78 50.32,132.32 50.32,132.32 50.32,132.89 52.93,135.51 67.03,135.51 72.95,141.43 J16.7 v1(84.91,141.43) ; v1(91.74,155.32) 88.87,152.45 v1(88.8,152.45)
  BOTTOM w0.381: v1(95.94,161.32) 112.99,161.32 113.01,161.33 v1(113.63,161.33) ; v1(88.8,152.45) 87.2,150.85 87.2,143.09 85.53,141.43 v1(84.91,141.43) ; v1(91.74,155.32) 93.22,156.79 v1(95,156.79) ; v1(100.94,119.35) 100.32,119.35 100.31,119.35 v1(96.72,119.35) ; v1(100.58,147.24) v1(97.38,147.24)
/CS_O_1: length 177.1
  TOP w0.381: v1(122.99,89.97) 121.81,89.97 121.8,89.98 U209.4 ; v1(235.59,76.25) 234.84,75.5 234.3,75.5 234.01,75.79 U65.8 ; U98.8 266.55,75.79 266.84,75.5 267.38,75.5 v1(268.12,76.25)
  BOTTOM w0.381: v1(122.99,89.97) 132.87,89.97 146.2,76.63 156.9,76.63 162.53,70.99 164.26,70.99 168.15,74.88 192.81,74.88 196.55,71.15 198.7,71.15 209.3,81.74 228.75,81.74 234.24,76.25 v1(235.59,76.25) 241.07,81.74 261.8,81.74 267.28,76.25 v1(268.12,76.25)
/CS_O_2: length 175.1
  TOP w0.381: v1(235.59,107.92) 234.84,107.18 234.3,107.18 234.01,107.47 U74.8 ; U106.8 266.55,107.47 266.84,107.18 267.38,107.18 v1(268.12,107.92) ; v1(123.44,118.14) 120.36,118.14 120.36,118.14 U211.4
  BOTTOM w0.381: v1(268.12,107.92) 263.42,112.62 240.28,112.62 ; v1(123.44,118.14) 124.97,116.61 157.23,116.61 163.53,110.31 165.02,110.31 170.31,115.6 192.41,115.6 200.99,107.01 203.25,107.01 209.32,113.08 239.83,113.08 240.28,112.62 ; 240.28,112.62 v1(235.59,107.92)
/CS_O_3: length 183.3
  TOP w0.381: U81.8 234.01,141.73 234.3,141.44 234.84,141.44 v1(235.59,142.19) ; U114.8 266.55,141.73 266.84,141.44 267.38,141.44 v1(268.12,142.19) ; U213.4 122.85,146.3 122.85,146.31 v1(123.54,146.31)
  BOTTOM w0.381: v1(268.12,142.19) 257.45,152.86 246.25,152.86 v1(235.59,142.19) 231.32,142.19 217.81,155.7 208.74,155.7 202.41,149.38 199.31,149.38 192.68,156.01 169.6,156.01 165.13,151.54 163.22,151.54 157.63,157.12 145.95,157.12 135.13,146.31 v1(123.54,146.31)
/CS_O_4: length 194.8
  TOP w0.381: v1(235.59,176.23) 234.84,175.48 234.3,175.48 234.01,175.77 U90.8 ; U122.8 266.55,175.77 266.84,175.48 267.38,175.48 v1(268.12,176.23) ; v1(123.75,160.4) 122.97,160.4 122.96,160.39 U215.4
  BOTTOM w0.381: v1(268.12,176.23) 267.46,176.23 260.1,183.59 242.95,183.59 v1(235.59,176.23) 214.96,196.85 190.4,196.85 184.23,190.68 164.26,190.68 159.72,186.13 159.72,168.76 158.17,167.21 146.61,167.21 139.8,160.4 v1(123.75,160.4)
A_GND: length 3136.2
  TOP w0.254: v1(36.81,122.74) U300.160 ; 41.81,131.44 U300.91 ; 41.81,131.44 v1(41.81,132.33) ; 41.81,131.44 42.31,130.94 U300.92 ; 47.81,131.53 v1(47.81,132.33) ; 47.81,131.53 48.31,131.03 U300.104 ; 47.81,131.53 U300.103 ; 36.81,91.26 36.8,91.25 v1(36.8,90.32) ; 36.81,91.26 37.31,91.76 U300.79 ; 36.81,91.26 U300.80 ; 55.32,123.42 54.81,123.93 U300.124 ; 55.32,123.42 55.31,123.43 U300.123 ; 55.32,123.42 v1(55.32,122.81) ; 45.31,89.21 44.81,89.71 U300.64 ; 45.31,89.21 U300.63 ; 45.31,89.21 v1(45.31,88.19) ; 36.8,123.37 37.31,123.88 U300.159 ; 44.81,123.52 44.81,123.51 v1(44.81,122.71) ; 44.81,123.52 U300.144 ; 44.81,123.52 44.81,123.52 45.31,124.02 U300.143 ; U300.13 42.81,98.79 43.31,99.29 43.31,99.65 ; 43.31,99.65 v1(43.31,99.8) ; 43.31,99.65 U300.14 ; v1(56.24,90.14) 55.31,91.07 U300.43 ; v1(54.58,88.85) 53.81,89.62 U300.46
  TOP w0.381: C136.1 262.7,113.77 263.45,114.51 v1(263.45,114.99) ; U131.3 33.88,48.3 34.3,47.88 v1(34.98,47.88) ; 261.62,100.51 v1(261.62,102.51) ; U115.3 263.98,139.09 263.18,139.89 ; 19.13,172.85 19.08,172.9 v1(19.08,174.93) ; C154.1 262.7,182.07 263.45,182.81 v1(263.45,183.29) ; U132.3 40.72,48.3 41.31,47.7 v1(41.83,47.7) ; v1(187.59,177.4) 189.54,177.4 C80.1 ; U121.7 264.22,187.1 264.69,187.57 v1(264.69,187.66) ; v1(124.87,47.12) 125.31,46.68 125.31,45.25 U152.3 ; 231.44,103.25 231.44,104.83 230.65,105.62 ; C36.1 v1(152.37,165.69) ; C223.2 66.93,49.17 68.58,47.52 v1(69.01,47.52) ; J10.5 231.19,15.37 231.19,20.12 230.43,20.88 ; 263.18,105.62 263.98,104.83 263.98,103.25 ; 263.18,105.62 263.18,106.16 263.19,106.16 263.19,106.32 v1(263.63,106.76) ; 263.18,105.62 U104.1 ; v1(121.67,114.66) 120.9,114.66 120.37,114.12 U169.3 ; C24.1 v1(163.04,105.38) ; v1(232.16,153.62) 232.16,153.53 231.69,153.06 U83.7 ; v1(79.12,47.85) 78.24,47.85 77.8,48.3 U141.3 ; C241.2 116.05,88.34 v1(114.43,89.97) 116.8,89.97 U209.3 ; C213.2 22.94,49.28 24.59,47.62 24.59,47.61 v1(25.03,47.17) ; v1(232.16,87.68) 232.16,87.59 231.69,87.12 U66.7 ; 192.18,36.83 192.18,36.86 v1(193.01,37.69) ; C195.2 v1(121.54,137.54) ; v1(263.63,175.06) 263.19,174.62 263.19,174.46 263.18,174.46 263.18,173.92 ; U204.3 115.1,132.22 114.76,131.88 v1(114.76,130.84) 114.76,130.81 115.14,130.43 C188.2 ; v1(92.23,46.61) 92.55,46.29 92.55,45.24 ; 263.18,139.89 263.18,140.43 263.19,140.43 263.19,140.58 v1(263.63,141.02) ; 263.18,139.89 U112.1 ; C200.2 v1(114.91,144.6) 114.91,145.52 115.7,146.3 U213.3 ; v1(28.55,39.12) 27.36,40.31 C210.2 ; v1(65.38,47.85) 64.5,47.85 64.06,48.3 U139.3 ; 230.65,73.95 U64.1 ; 230.65,73.95 230.65,74.49 230.65,74.49 230.65,74.64 v1(231.09,75.08) ; 230.65,73.95 231.44,73.15 U67.3 ; v1(152.03,95.44) 154.06,95.44 C20.1 ; v1(233.55,139.9) 232.73,140.72 232.73,140.85 232.71,140.87 U81.6 ; C91.1 230.17,82.09 230.62,82.55 230.62,82.57 230.73,82.67 230.73,82.69 v1(231.17,83.13) ; U157.3 133.04,53.32 v1(132.82,53.54) ; C102.1 v1(227.1,97.28) ; U136.3 v1(68.99,39.09) ; C41.1 v1(164.26,167.74) ; C100.1 230.32,113.77 230.91,114.36 v1(230.91,114.98) ; C156.1 v1(259.64,165.58) ; C187.2 v1(112.09,134.82) ; U104.3 257.84,106.27 v1(257.45,106.65) ; U6.2 v1(157.38,73.08) ; C97.1 v1(240.08,96.24) ; C238.2 125.45,52.68 v1(124.56,53.57) ; U149.3 v1(106.22,53.34) ; C76.1 v1(188,165.69) ; v1(152.15,54.82) 154.06,54.82 C10.1 ; U205.3 106.69,143.41 105.69,142.41 v1(105.69,141.73) C189.2 ; v1(188.29,142.65) 189.09,143.44 C67.1 ; C212.2 41.12,39.9 v1(41.86,39.17) ; C217.2 v1(51.05,40.82) ; U178.3 115.19,153.34 114.4,152.55 v1(114.4,151.56) C199.2 ; C17.1 153.89,102.9 v1(152.81,101.82) ; 178.05,18.9 J3.10 ; U138.3 57.15,48.3 57.59,47.85 v1(58.47,47.85) ; C87.1 v1(240.08,64.57) ; C27.1 153.81,143.44 v1(152.7,142.34) ; C40.1 v1(152.32,177.27) ; U114.6 265.25,140.87 265.27,140.85 265.27,140.72 v1(266.09,139.9) ; C74.1 v1(198.53,146.43) ; J14.3 251.54,15.34 251.54,19.79 ; C60.1 189.54,95.44 v1(187.65,95.44) ; v1(55.22,47.55) 54.6,47.55 52.93,49.21 C221.2 ; v1(48.77,47.9) 47.94,47.9 47.55,48.3 U133.3 ; U129.3 45.34,39.87 45.35,39.86 v1(45.35,39.03) ; U20.2 v1(157.33,154.23) ; v1(231.09,175.06) 230.65,174.62 230.65,174.46 230.65,174.46 230.65,173.92 ; v1(118.77,53.29) 119.56,52.5 C237.2 ; v1(231.09,141.02) 230.65,140.58 230.65,140.43 230.65,140.43 230.65,139.89 ; U113.7 264.22,153.06 264.69,153.53 v1(264.69,153.62) ; v1(119.1,46.69) 119.41,46.37 U151.3 ; U175.3 v1(121.36,169.88) ; C216.2 43.46,49.21 v1(45.48,47.19) ; U155.3 v1(121.28,53.37) ; J7.8 198.37,18.36 199.34,19.33 ; U214.3 106.69,177.76 105.59,176.65 v1(105.59,176) C203.2 ; U120.3 258.25,174.57 v1(257.56,175.27) ; C120.1 v1(227.1,165.58) ; C191.2 v1(100.05,162.33) 100.05,163.3 100.77,164.02 U206.3 ; C214.2 29.77,49.25 v1(31.67,47.35) ; U34.2 v1(192.94,73.08) ; U153.3 131.18,46.59 v1(130.68,47.09) ; U80.3 225.27,140.54 v1(224.82,141) ; U207.3 115.86,174.47 115.04,173.64 115.04,172.75 v1(115.06,172.72) C192.2 ; U201.3 106.11,88.46 106.11,88.47 v1(105.28,88.47) 105.72,88.03 105.72,88.02 107.02,86.72 C183.2 ; C5.1 v1(152.52,43.11) ; v1(230.91,149.25) 230.91,148.78 230.17,148.03 C109.1 ; C30.1 152.4,135.84 v1(152.25,135.99) ; v1(28.45,47.5) 27.83,47.5 27.05,48.27 U130.3 ; C84.1 v1(198.53,187.53) ; v1(264.69,87.68) 264.69,87.59 264.22,87.12 U97.7 ; C151.1 v1(272.62,164.54) ; J3.8 175.51,17.91 174.33,19.09 ; U144.3 98.48,45.26 98.48,46.17 v1(98.04,46.61) ; v1(158.99,159.58) 159.72,158.85 ; C54.1 v1(198.53,65.13) ; v1(263.45,149.25) 263.45,148.78 262.7,148.03 C145.1 ; v1(58.5,39.14) 57.96,39.67 C218.2 ; U122.6 265.25,174.9 265.27,174.89 265.27,174.76 v1(266.09,173.94) ; v1(31.62,38.91) 31.62,42.55 U127.3 ; 230.65,105.62 230.65,106.16 230.65,106.16 230.65,106.32 v1(231.09,106.76) ; 230.65,105.62 U72.1 ; C229.2 98.63,52.46 v1(97.6,53.49) ; 86.66,45.24 86.66,46.23 v1(86.28,46.61) ; v1(103.71,53.37) 104.6,52.48 C230.2 ; C198.2 v1(105.46,121.06) 105.44,121.08 105.44,122.02 106.22,122.81 U210.3 ; C190.2 v1(111.71,169.11) ; U72.3 225.72,106.27 v1(225.2,106.79) ; C81.1 v1(199.75,168.17) ; C57.1 189.11,102.9 v1(188.29,102.08) ; 263.18,73.95 263.18,74.49 263.19,74.49 263.19,74.64 v1(263.63,75.08) ; 263.18,73.95 U96.1 ; 263.18,73.95 263.98,73.15 U99.3 ; U48.2 v1(192.96,154.23) ; C16.1 v1(152.36,83.73) ; C215.2 36.68,49.12 v1(38.63,47.17) ; v1(113.16,46.63) 113.53,46.26 U150.3 ; J3.3 169.16,15.37 165.4,15.37 ; 230.65,139.89 231.44,139.09 U82.3 ; 230.65,139.89 U80.1 ; 261.62,69.62 v1(261.62,70.79) ; C219.2 64.9,39.65 v1(65.41,39.14) ; U64.3 225.65,74.6 v1(225.2,75.06) ; J14.10 260.4,18.11 261.75,19.46 ; J14.5 254.05,15.37 254.05,18.81 ; U156.3 v1(127.16,53.56) ; U105.7 264.22,118.8 264.69,119.27 v1(264.69,119.35) ; C133.1 v1(272.62,96.24) ; C211.2 34.11,40.01 v1(35.13,38.99) ; v1(130.43,53.52) 131.37,52.58 C239.2 ; C138.1 v1(259.64,97.28) ; C182.2 v1(114.6,73.89) 114.6,74.85 115.65,75.9 U200.3 ; C208.2 v1(105.56,182.83) 105.56,183.5 106.69,184.63 U183.3 ; C111.1 v1(227.1,131.55) ; U120.1 263.18,173.92 ; 263.18,173.92 263.98,173.13 U123.3 ; v1(229.21,169.98) 229.21,168.73 ; C51.1 v1(199.75,45.03) ; 187.32,15.85 187.81,15.37 192.02,15.37 J7.3 ; C37.1 153.81,184.87 v1(152.73,183.79) ; C31.1 v1(164.26,126.77) ; U146.3 v1(88.57,53.42) ; 261.7,169.72 v1(261.7,171.07) ; C185.2 115.9,102.13 v1(114.58,103.45) 115.06,103.94 U202.3 ; U89.7 231.69,187.1 232.16,187.57 v1(232.16,187.66) ; v1(76.15,47.52) 75.46,47.52 73.74,49.25 C224.2 ; C71.1 v1(199.75,126.29) ; C209.2 20.46,42.05 20.46,41.3 v1(20.44,41.28) ; J10.8 235,19.13 ; v1(72.31,39.14) 71.73,39.73 C220.2 ; C61.1 v1(199.75,85.55) ; C243.2 115.67,94.95 v1(113.82,96.8) U176.3 ; U137.3 v1(75.82,39.09) ; C115.1 v1(240.08,164.54) ; v1(188.34,184.02) 189.19,184.87 C77.1 ; v1(158.88,77.85) 159.49,77.24 ; C124.1 v1(272.62,64.57) ; U173.3 v1(112.14,111.48) ; v1(187.67,135.97) 189.54,135.97 C70.1 ; v1(188.26,61.24) 189.31,62.29 C47.1 ; 230.65,173.92 U88.1 ; 230.65,173.92 231.44,173.13 U91.3 ; U74.6 232.71,106.6 232.73,106.59 232.73,106.46 v1(233.55,105.64) ; C222.2 59.97,49.15 61.48,47.64 62.02,47.64 v1(62.08,47.7) ; U140.3 70.97,48.3 71.41,47.85 v1(72.29,47.85) ; U98.6 265.25,74.93 265.27,74.91 265.27,74.79 v1(266.09,73.96) ; v1(38.5,39.13) 38.5,39.75 38.51,39.76 U128.3 ; 229.21,69.01 v1(229.21,70.21) ; v1(233.55,173.94) 232.73,174.76 232.73,174.89 232.71,174.9 U90.6 ; v1(266.09,105.64) 265.27,106.46 265.27,106.59 265.25,106.6 U106.6 ; U27.2 v1(157.4,195.66) ; 258.34,19.63 257.86,19.15 J14.8 ; C147.1 v1(259.64,131.55) ; 194.56,18.29 194.56,15.37 J7.5 ; v1(232.16,119.35) 232.16,119.27 231.69,118.8 U73.7 ; C46.1 v1(187.67,43.11) ; C201.2 v1(105.41,148.62) 105.41,149.58 106.11,150.28 U212.3 ; U65.6 232.71,74.93 232.73,74.91 232.73,74.79 v1(233.55,73.96) ; 170.43,19.05 171.7,17.78 171.7,15.37 J3.5 ; v1(152.68,61.29) 153.68,62.29 C7.1 ; U180.3 106.21,102.2 105.36,101.35 v1(105.36,100.33) C205.2 ; C186.2 106.81,114.15 v1(105.89,115.06) 106.77,115.94 U203.3 ; C66.1 v1(188.15,124.26) ; C129.1 v1(259.64,65.61) ; U177.3 115.76,125.18 v1(114.73,124.16) 115.49,123.39 C244.2 ; C196.2 v1(121.31,165.71) ; v1(103.99,46.61) 103.99,46.58 104.32,46.25 104.32,45.24 ; U179.3 115.86,181.51 114.99,180.63 v1(114.99,179.73) C202.2 ; C64.1 v1(198.53,105.23) ; C12.1 v1(164.26,44.75) ; U215.3 114.95,160.39 114.2,159.64 v1(114.2,158.65) C204.2 ; C106.1 v1(240.08,130.51) ; v1(115.42,53.42) 115.39,53.39 U154.3 ; C127.1 262.7,82.09 263.45,82.84 v1(263.45,83.31) ; 195.5,118.01 v1(194.75,118.76) ; U135.3 v1(62.08,39.09) ; C50.1 189.54,54.82 v1(187.64,54.82) ; v1(194.67,78.08) 195.3,77.44 ; C14.1 v1(163.04,64.97) ; C34.1 v1(163.04,146.33) ; C232.2 92.74,52.45 v1(91.77,53.42) ; C231.2 110.44,52.63 v1(109.73,53.34) ; v1(136.08,53.7) 137.29,52.49 C240.2 ; 201.6,18.82 200.91,18.14 J7.10 ; U168.3 v1(112.29,84.04) ; C193.2 v1(122.12,81.15) ; C197.2 115.47,116.51 v1(114.6,117.37) 115.37,118.14 U211.3 ; 158.09,36.25 v1(158.09,37.47) ; C26.1 v1(152.03,124.26) ; C194.2 v1(112.04,107.21) ; 227.36,20.24 228.68,18.92 228.68,15.34 J10.3 ; C93.1 v1(227.1,65.61) ; U126.3 v1(24.84,39.4) ; U55.2 v1(192.86,195.66) ; v1(230.91,183.29) 230.91,182.81 230.17,182.07 C118.1 ; U208.3 106.35,95.33 105.61,94.59 v1(105.61,93.65) C242.2 ; 229.18,134.92 v1(229.18,136.47) ; U171.3 v1(112.01,173.34) ; v1(159.74,118.36) 160.52,117.59 ; v1(194.74,160.17) 195.71,159.21 ; U112.3 258.25,140.54 v1(257.61,141.19) ; U88.3 225.55,174.57 v1(225.04,175.08) ; U181.3 106.53,129.67 105.59,128.73 v1(105.59,127.89) C206.2 ; C21.1 v1(164.26,86.28) ; C184.2 v1(121.72,110.01) ; U182.3 106.27,157.15 105.44,156.31 v1(105.44,155.37) C207.2 ; U174.3 v1(121.53,141.71) ; C56.1 v1(187.62,83.73) ; U134.3 v1(55.17,39.09) ; U96.3 258.17,74.6 v1(257.58,75.18) ; v1(261.57,136.75) 261.57,135.48 ; C44.1 v1(163.04,187.66) ; U170.3 v1(112.11,138.99) ; C142.1 v1(272.62,130.51) ; U13.2 v1(157.33,113.69) ; U172.3 v1(122.09,85.39) ; C181.2 v1(112.24,79.76) ; U41.2 v1(192.94,113.69) ; U147.3 v1(94.45,53.45) ; U148.3 v1(100.34,53.5) ; 229.21,100.61 v1(229.21,102.16)
  TOP w0.762: 159.72,158.85 178.82,139.75 178.82,33.73 178.05,32.97 178.05,18.9 ; 229.21,168.73 229.21,164.21 249.61,143.81 249.61,62.76 237.54,50.7 J10.10 ; 158.09,36.25 158.09,20.78 163.5,15.37 165.4,15.37 ; 170.43,19.05 168.76,20.73 165.84,20.73 165.07,21.49 165.07,32.72 170.03,37.67 170.03,66.7 159.49,77.24 ; 261.57,135.48 261.57,128.75 278.36,111.96 278.36,56.18 260.17,38 260.17,21.46 258.34,19.63 ; 261.7,169.72 261.7,162.28 282.5,141.48 282.5,56.41 265.39,39.31 265.39,23.1 261.75,19.46 ; 254.05,18.81 255.12,19.88 255.12,36.5 274.9,56.29 274.9,82.83 261.62,96.11 261.62,100.51 ; 251.54,19.79 248.95,22.38 248.95,36.22 261.62,48.9 261.62,69.62 ; 230.43,20.88 227.09,24.22 227.09,47.21 243.56,63.68 243.56,81.94 229.21,96.29 229.21,100.61 ; 194.56,18.29 194.56,32.26 207.14,44.83 207.14,65.61 195.3,77.44 ; 195.71,159.21 214.68,140.23 214.68,40.64 207.31,33.27 207.31,20.22 205.92,18.82 201.6,18.82 ; 195.5,118.01 210.64,102.87 210.64,42.27 201.17,32.79 201.17,21.16 199.34,19.33 ; 227.36,20.24 222.33,25.27 222.33,52.86 229.21,59.74 229.21,69.01 ; 235,19.13 235,21.06 232.33,23.72 232.33,48.67 246.53,62.87 246.53,112.67 229.18,130.02 229.18,134.92 ; 192.18,36.83 187.32,31.98 187.32,15.85 ; 160.52,117.59 173.63,104.47 173.63,34.26 171.56,32.19 171.56,21.86 174.33,19.09
  TOP w1.27: U303.3 16.11,167.93 16.13,167.95 16.13,168.73 17.32,169.93 ; 22.2,165.95 22.2,168.63 20.9,169.93
  TOP w2.032: 19.13,172.85 19.13,169.93 ; 19.13,169.93 17.32,169.93 ; 19.13,169.93 20.9,169.93
  GND w0.127: J9.1 91.34,14.97 ; J9.1 92.22,14.1 ; J9.1 91.34,13.22 ; J9.1 90.46,14.1 ; J1.1 33.77,14.1 ; J1.1 32.02,14.1 ; J1.1 32.89,14.97 ; J1.1 32.89,13.22 ; J13.1 115.08,14.1 ; J13.1 114.2,14.97 ; J13.1 113.32,14.1 ; J13.1 114.2,13.22 ; 226.5,14.1 J10.1 ; J10.1 228.26,14.1 ; J10.1 227.38,14.97 ; J10.1 227.38,13.22 ; 126.02,16.64 J13.12 ; J13.12 126.9,15.76 ; J13.12 127.78,16.64 ; J13.12 126.9,17.51 ; U301.3 40.09,173.41 ; U301.3 41.1,172.39 ; U301.3 39.07,172.39 ; U301.3 40.09,171.37 ; J10.12 240.96,16.64 ; J10.12 240.08,17.51 ; J10.12 239.2,16.64 ; J10.12 240.08,15.76 ; J16.11 82.17,152.46 ; J16.11 81.29,151.59 ; J16.11 83.05,151.59 ; J16.11 82.17,150.71 ; 67.58,16.64 J5.12 ; J5.12 68.45,17.51 ; J5.12 69.33,16.64 ; J5.12 68.45,15.76 ; U302.3 41.1,147.01 ; U302.3 40.09,148.03 ; U302.3 40.09,146 ; U302.3 39.07,147.01 ; U301.2 37.55,173.41 ; U301.2 38.56,172.39 ; U301.2 37.55,171.37 ; U301.2 36.53,172.39 ; 82.17,121.45 J15.12 ; J15.12 81.29,122.33 ; J15.12 82.17,123.2 ; J15.12 83.05,122.33 ; 104.04,15.76 J9.12 ; J9.12 104.92,16.64 ; J9.12 103.16,16.64 ; J9.12 104.04,17.51 ; 81.29,154.13 J16.12 ; J16.12 82.17,155 ; J16.12 82.17,153.25 ; J16.12 83.05,154.13 ; 189.88,14.1 J7.1 ; J7.1 190.75,14.97 ; J7.1 190.75,13.22 ; J7.1 191.63,14.1 ; J14.1 250.24,14.97 ; J14.1 251.12,14.1 ; J14.1 250.24,13.22 ; J14.1 249.36,14.1 ; U301.9 55.33,173.41 ; U301.9 55.33,171.37 ; U301.9 56.34,172.39 ; U301.9 54.31,172.39 ; 82.17,118.91 J15.11 ; J15.11 82.17,120.66 ; J15.11 81.29,119.79 ; J15.11 83.05,119.79 ; 179.72,16.64 J3.12 ; J3.12 180.59,15.76 ; J3.12 181.47,16.64 ; J3.12 180.59,17.51 ; J3.1 167.89,14.97 ; J3.1 168.77,14.1 ; J3.1 167.02,14.1 ; J3.1 167.89,13.22 ; J5.1 56.63,14.1 ; J5.1 55.75,14.97 ; J5.1 54.88,14.1 ; J5.1 55.75,13.22 ; 19.53,141.57 J17.1 ; J17.1 18.66,142.44 ; J17.1 20.41,142.44 ; U301.16 56.34,187.63 ; U301.16 55.33,188.65 ; U301.16 55.33,186.61 ; U301.16 54.31,187.63 ; 203.45,15.76 J7.12 ; J7.12 202.58,16.64 ; J7.12 204.33,16.64 ; J7.12 203.45,17.51 ; 18.66,144.98 J17.2 ; J17.2 20.41,144.98 ; J17.2 19.53,145.86 ; J18.1 16.5,181.84 ; J18.1 14.74,181.84 ; J18.1 15.62,180.96 ; U302.2 38.56,147.01 ; U302.2 36.53,147.01 ; U302.2 37.55,148.03 ; U302.2 37.55,146 ; J14.12 262.94,17.51 ; J14.12 262.06,16.64 ; J14.12 262.94,15.76 ; J14.12 263.82,16.64 ; J18.2 16.5,184.38 ; J18.2 15.62,185.26 ; J18.2 14.74,184.38 ; J1.12 46.47,16.64 ; J1.12 45.59,17.51 ; J1.12 44.72,16.64 ; J1.12 45.59,15.76
  GND w0.381: J18.1 J18.2
  GND w0.635: J17.2 J17.1
  BOTTOM w0.381: U1.1 177.03,172.21 177.65,172.83 177.65,173.81 179.55,175.72 ; C172.2 78.02,39.13 78.03,39.14 ; D26.A 252.76,37.78 253.66,38.68 v1(254.43,38.68) 256.54,38.68 256.57,38.71 256.76,38.71 257.68,37.78 D28.A ; v1(268.58,66.62) 268.58,67.44 268.96,67.82 U95.1 ; C119.1 221.55,165.66 v1(219.13,165.66) 217.81,166.98 217.81,168.74 218.35,169.29 U93.2 ; U40.1 186.89,104.34 187.16,104.61 187.16,105.15 v1(186.3,106.01) ; C180.1 187.45,192.56 v1(186.59,191.69) ; C167.2 68.02,38.09 68.05,38.11 68.05,39.09 ; U92.2 218.35,176.68 217.98,176.31 217.98,174.47 v1(219.3,173.15) C117.1 ; v1(100.71,26.62) 101.23,26.62 102.03,27.42 D78.A ; C227.2 96.75,46.13 97.21,46.58 97.4,46.58 97.42,46.61 v1(98.04,46.61) ; U196.1 57.18,55.64 57.72,56.18 v1(58.06,56.18) ; C176.1 v1(150.88,192.43) ; C42.1 167.36,177.29 168.55,176.1 v1(168.55,172.97) U30.2 ; v1(235.28,137.71) 236.46,138.89 C105.1 ; U53.1 v1(187.59,177.4) 186.58,178.41 C78.1 ; 37.62,39.09 37.62,39.99 37.44,40.17 R127.2 ; 37.62,39.09 C159.2 ; 37.62,39.09 38.46,39.09 v1(38.5,39.13) ; R30.2 v1(157.01,131.69) ; U185.1 30.04,54.22 v1(31.32,55.5) ; R66.2 v1(192.49,131.69) ; v1(124.87,47.12) 124.84,47.14 124.05,47.14 123.67,46.76 C235.2 ; C174.1 v1(151,110.62) ; C233.2 111.81,46.25 112.19,46.63 v1(113.16,46.63) ; C173.1 v1(151.13,70.03) ; C144.1 v1(251.84,139.12) 250.49,140.46 250.49,142.25 250.89,142.65 U116.2 ; U100.2 250.89,76.71 250.6,76.42 250.6,74.42 v1(251.84,73.18) C126.1 ; C99.1 v1(219.3,104.85) 217.96,106.2 217.96,107.99 218.35,108.38 U76.2 ; 47.93,38.94 47.93,39.73 47.5,40.17 R142.2 ; 47.93,38.94 v1(49.1,38.94) ; 47.93,38.94 C164.2 ; U16.2 v1(168.55,91.01) 168.55,94.13 167.36,95.33 C22.1 ; U166.1 198.86,26.47 198.32,25.93 v1(198.32,25.91) ; C170.2 64.28,39.13 64.29,39.14 ; C58.1 186.58,96.5 v1(187.65,95.44) U39.1 ; U63.1 236.42,67.82 236.04,67.44 v1(236.04,66.62) ; 44.53,39.09 45.29,39.09 v1(45.35,39.03) ; 44.53,39.09 44.53,39.79 44.15,40.17 R130.2 ; 44.53,39.09 C160.2 ; v1(115.65,26.09) 116.81,26.09 117.19,26.47 D90.A ; 40.79,39.19 40.79,38.42 41.12,38.09 C163.2 ; 40.79,39.19 41.83,39.19 v1(41.86,39.17) ; 40.79,39.19 R139.2 ; C48.1 186.58,55.88 v1(187.64,54.82) U32.1 ; U192.1 53.32,54.38 v1(54.64,55.7) ; v1(191.92,25.81) 192.58,26.47 U165.1 ; 179.55,175.72 179.55,174.98 179.58,174.96 C2.1 ; 179.55,175.72 v1(179.58,175.74) 178.21,177.11 C1.1 ; C15.1 v1(151.1,87.32) ; D92.A 123.02,27.42 122.15,26.54 v1(121.56,26.54) ; C88.1 236.46,72.95 v1(235.28,71.77) ; U24.2 v1(168.71,139.85) 168.71,142.09 167.06,143.74 C33.1 ; U198.1 70.98,55.64 71.5,56.16 v1(71.98,56.16) ; R133.2 27.38,40.17 27.64,39.91 27.64,39.12 ; U84.2 218.35,142.65 218.03,142.33 218.03,140.39 v1(219.3,139.12) C108.1 ; v1(186.3,146.45) 186.99,145.75 186.99,145.21 186.66,144.88 U47.1 ; D22.A 234.39,38.1 v1(235.64,39.34) ; U162.1 169.88,26.21 v1(169.21,25.55) ; v1(205,25.98) 205.51,26.49 U167.1 ; U23.2 v1(168.55,131.55) 168.55,134.67 167.36,135.86 C32.1 ; C161.2 27.64,39.12 ; 27.64,39.12 v1(28.55,39.12) ; 78.03,39.14 78.23,39.34 R166.2 ; 78.03,39.14 v1(79.15,39.14) ; C228.2 102.57,46.23 102.95,46.61 v1(103.99,46.61) ; U190.1 40.29,55.65 40.78,56.13 v1(41.4,56.13) ; R124.2 30.73,40.17 30.86,40.04 30.86,38.91 ; C101.1 221.57,97.38 v1(219.28,97.38) 218.03,98.63 218.03,100.67 218.35,100.99 U77.2 ; C236.2 129.54,46.75 129.88,47.09 v1(130.68,47.09) ; U46.1 v1(187.67,135.97) 186.58,137.07 C68.1 ; R121.2 24.03,39.4 ; 24.03,39.4 24.03,38.42 23.7,38.09 C157.2 ; 24.03,39.4 v1(24.84,39.4) ; U18.1 150.44,135.99 v1(152.25,135.99) 151.1,137.14 C28.1 ; U62.2 279.76,124.64 280.51,125.39 C85.1 v1(284.75,125.39) ; v1(94.95,26.59) 95.38,26.59 96.2,27.42 D76.A ; U108.2 250.89,108.38 250.6,108.09 250.6,106.1 v1(251.84,104.85) C135.1 ; v1(268.58,166.6) 268.58,167.41 268.96,167.79 U119.1 ; v1(150.83,65.33) 151.58,64.57 151.58,64.03 151.28,63.73 U5.1 ; U187.1 43.84,53.7 43.84,53.7 43.84,54.05 v1(44.96,55.17) ; C62.1 202.84,95.33 204.04,94.13 v1(204.04,91.01) U44.2 ; v1(72.31,39.14) 71.2,39.14 ; 71.2,39.14 71.19,39.13 C171.2 ; 71.2,39.14 71.4,39.34 R163.2 ; C150.1 269,172.92 v1(267.82,171.75) ; v1(58.5,39.14) 57.38,39.14 ; 57.38,39.14 57.37,39.13 C169.2 ; 57.38,39.14 57.58,39.34 R157.2 ; v1(132.66,26.42) 133.68,26.42 134.69,27.42 D96.A ; U54.1 186.74,186.31 187.05,186.61 187.05,187.15 v1(186.24,187.96) ; v1(124.66,26.54) 125.06,26.54 125.94,27.42 D86.A ; C90.1 v1(219.3,73.18) 218.03,74.45 218.03,76.39 218.35,76.71 U68.2 ; C86.1 v1(280.57,120.78) ; C162.2 34.21,38.99 ; 34.21,38.99 v1(35.13,38.99) ; 34.21,38.99 34.21,40.04 34.09,40.17 R136.2 ; U186.1 36.94,53.96 v1(38.23,55.24) ; D72.A 104.95,27.42 104.2,26.67 v1(103.56,26.67) ; U191.1 47.19,55.64 47.66,56.11 47.69,56.11 47.71,56.13 v1(48.34,56.13) ; v1(268.58,98.3) 268.58,99.11 268.96,99.49 U103.1 ; C165.2 54.2,38.09 54.23,38.11 54.23,39.09 ; U37.2 v1(204.04,50.39) 204.04,53.52 202.84,54.71 C52.1 ; U79.1 236.42,133.76 236.04,133.38 v1(236.04,132.56) ; U199.1 77.88,55.64 78.4,56.16 v1(78.94,56.16) ; U4.3 v1(168,170.15) ; U124.2 250.89,176.68 250.6,176.39 250.6,174.4 v1(251.84,173.15) C153.1 ; C226.2 90.91,46.18 91.34,46.61 v1(92.23,46.61) ; U9.2 v1(168.55,50.39) 168.55,53.52 167.36,54.71 C11.1 ; C63.1 202.54,103.2 204.19,101.55 v1(204.19,99.31) U45.2 ; 64.29,39.14 64.49,39.34 R160.2 ; 64.29,39.14 v1(65.41,39.14) ; v1(162.59,25.65) 162.59,25.68 163.12,26.21 U161.1 ; C13.1 167.06,62.59 168.71,60.93 v1(168.71,58.7) U10.2 ; v1(225.53,39.24) 224.46,38.18 D18.A ; U31.2 v1(168.71,181.28) 168.71,183.51 167.06,185.17 C43.1 ; U61.2 149.01,27.02 149.33,27.33 149.96,27.33 150.93,26.37 v1(150.93,25.65) 150.93,23.52 150.42,23.01 148.69,23.01 148.36,23.34 U61.3 ; C123.1 269,72.95 v1(267.82,71.77) ; C179.1 v1(185.88,151.16) ; U3.2 v1(176.15,163.58) ; R12.2 v1(157.24,50.54) ; C166.2 61.11,38.09 61.14,38.11 61.14,39.09 ; U109.2 250.89,100.99 250.6,100.7 250.6,98.53 v1(251.84,97.28) 254.01,97.28 C137.1 ; D68.A 93.28,27.42 92.51,26.64 v1(91.92,26.64) ; v1(65.13,56.13) 64.57,56.13 64.08,55.64 U197.1 ; 54.23,39.09 v1(55.17,39.09) ; 54.23,39.09 R145.2 ; C35.1 v1(151.1,169.74) ; U17.2 v1(168.71,99.31) 168.71,101.55 167.06,103.2 C23.1 ; C158.2 30.86,38.91 ; 30.86,38.91 v1(31.62,38.91) ; D30.A 262.66,37.78 263.31,38.43 263.7,38.43 263.73,38.46 v1(266.88,38.46) 267.5,38.46 268.17,37.78 D32.A ; U58.2 v1(204.04,172.97) 204.04,176.1 202.84,177.29 C82.1 ; C132.1 269,104.62 v1(267.82,103.45) ; v1(62.08,39.09) 61.14,39.09 ; 61.14,39.09 R148.2 ; C141.1 269,138.89 v1(267.82,137.71) ; U160.1 v1(154.23,26.21) ; C65.1 v1(186.58,128.1) ; v1(118.49,26.21) 119.22,26.21 120.11,27.1 D84.A ; v1(186.32,65.32) 187.1,64.55 187.1,64.01 186.82,63.73 U33.1 ; C146.1 254.09,131.62 v1(251.61,131.62) 250.55,132.69 250.55,134.91 250.89,135.25 U117.2 ; D20.A 229.39,38.15 v1(230.71,39.47) ; U60.2 147.52,33.71 v1(147.98,33.25) ; D66.A 87.45,27.42 86.68,26.64 v1(86.33,26.64) ; D80.A 107.86,27.42 107.17,26.72 v1(106.63,26.72) ; v1(236.04,98.3) 236.04,99.11 236.42,99.49 U71.1 ; v1(235.28,171.75) 236.46,172.92 C114.1 ; C25.1 v1(151.1,128.3) ; v1(75.82,39.09) 74.88,39.09 ; 74.88,39.09 R154.2 ; 74.88,39.09 74.88,38.11 74.85,38.09 C168.2 ; C178.1 v1(186.18,110.9) ; v1(176.12,25.58) 176.76,26.21 U163.1 ; C83.1 202.54,185.17 204.19,183.51 v1(204.19,181.28) U59.2 ; D70.A 99.12,27.42 98.29,26.59 v1(97.89,26.59) ; C225.2 84.86,46.15 85.32,46.61 v1(86.28,46.61) ; v1(75.64,54.97) 74.66,54.97 74.02,54.32 U195.1 ; D74.A 90.37,27.42 89.59,26.64 v1(89.28,26.64) ; D88.A 131.77,27.42 130.74,26.39 v1(130.25,26.39) ; C8.1 151.1,55.88 v1(152.15,54.82) U2.1 ; U19.1 151.38,144.88 151.65,145.15 151.65,145.69 v1(150.94,146.4) ; D24.A 239.88,37.9 v1(241.4,39.42) ; U11.1 v1(152.03,95.44) 152.03,96.06 151.1,96.99 C18.1 ; R75.2 v1(192.75,173.12) ; U12.1 151.33,104.34 151.64,104.65 151.64,105.19 v1(150.73,106.1) ; v1(236.04,166.6) 236.04,167.41 236.42,167.79 U87.1 ; C110.1 221.49,131.72 v1(219.28,131.72) 217.96,133.05 217.96,134.86 218.35,135.25 U85.2 ; R57.2 v1(192.75,91.15) ; C96.1 236.46,104.62 v1(235.28,103.45) ; 251.84,169.29 250.89,169.29 250.47,168.87 250.47,166.97 v1(251.76,165.68) C155.1 ; 68.05,39.09 v1(68.99,39.09) ; 68.05,39.09 R151.2 ; v1(127.13,26.44) 127.88,26.44 128.85,27.42 D94.A ; R48.2 v1(192.52,50.54) ; U111.1 268.96,133.76 268.58,133.38 v1(268.58,132.56) ; U189.1 33.39,55.64 33.89,56.13 v1(34.44,56.13) ; v1(68.58,54.94) 67.81,54.94 67.12,54.25 U194.1 ; U26.1 151.21,186.31 151.53,186.64 151.53,187.18 v1(150.76,187.95) ; U25.1 150.55,177.27 v1(152.32,177.27) 151.1,178.49 C38.1 ; v1(112.7,26.16) 113.45,26.16 114.27,26.98 D82.A ; R21.2 v1(156.96,91.15) ; C73.1 202.54,143.74 204.19,142.09 v1(204.19,139.85) U52.2 ; C175.1 v1(150.7,151.16) ; U69.2 218.35,69.32 217.96,68.92 217.96,66.88 v1(219.23,65.61) 221.48,65.61 C92.1 ; U4.2 v1(167.35,164.83) ; U193.1 60.22,54.18 61.2,55.17 v1(62.13,55.17) ; U38.2 v1(204.19,58.7) 204.19,60.93 202.54,62.59 C53.1 ; U101.2 250.82,69.32 250.34,68.83 250.34,67.11 v1(251.71,65.74) 254.08,65.74 C128.1 ; C4.1 v1(151.1,46.98) ; v1(27.64,56.06) 26.91,56.06 26.49,55.64 U188.1 ; C45.1 v1(186.58,46.6) ; U164.1 186.41,26.44 v1(185.78,25.81) ; C55.1 v1(186.58,87.62) ; C72.1 202.84,135.86 204.04,134.67 v1(204.04,131.55) U51.2 ; C75.1 v1(186.58,169.38) ; U184.1 23.14,53.87 v1(22.4,54.61) ; C177.1 v1(185.9,70.1) ; R39.2 v1(157.32,173.12) ; v1(119.1,46.69) 118.16,46.69 117.73,46.25 C234.2
